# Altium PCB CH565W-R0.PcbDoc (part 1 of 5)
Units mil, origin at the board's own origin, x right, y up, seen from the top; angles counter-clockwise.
Board outline 3947.04 x 3947.04 mil, 4 copper layers (Top Layer, Layer 1, Layer 2, Bottom Layer), stack 23.756 mil thick; 204 components, 168 nets, 932 pads, 1005 vias.
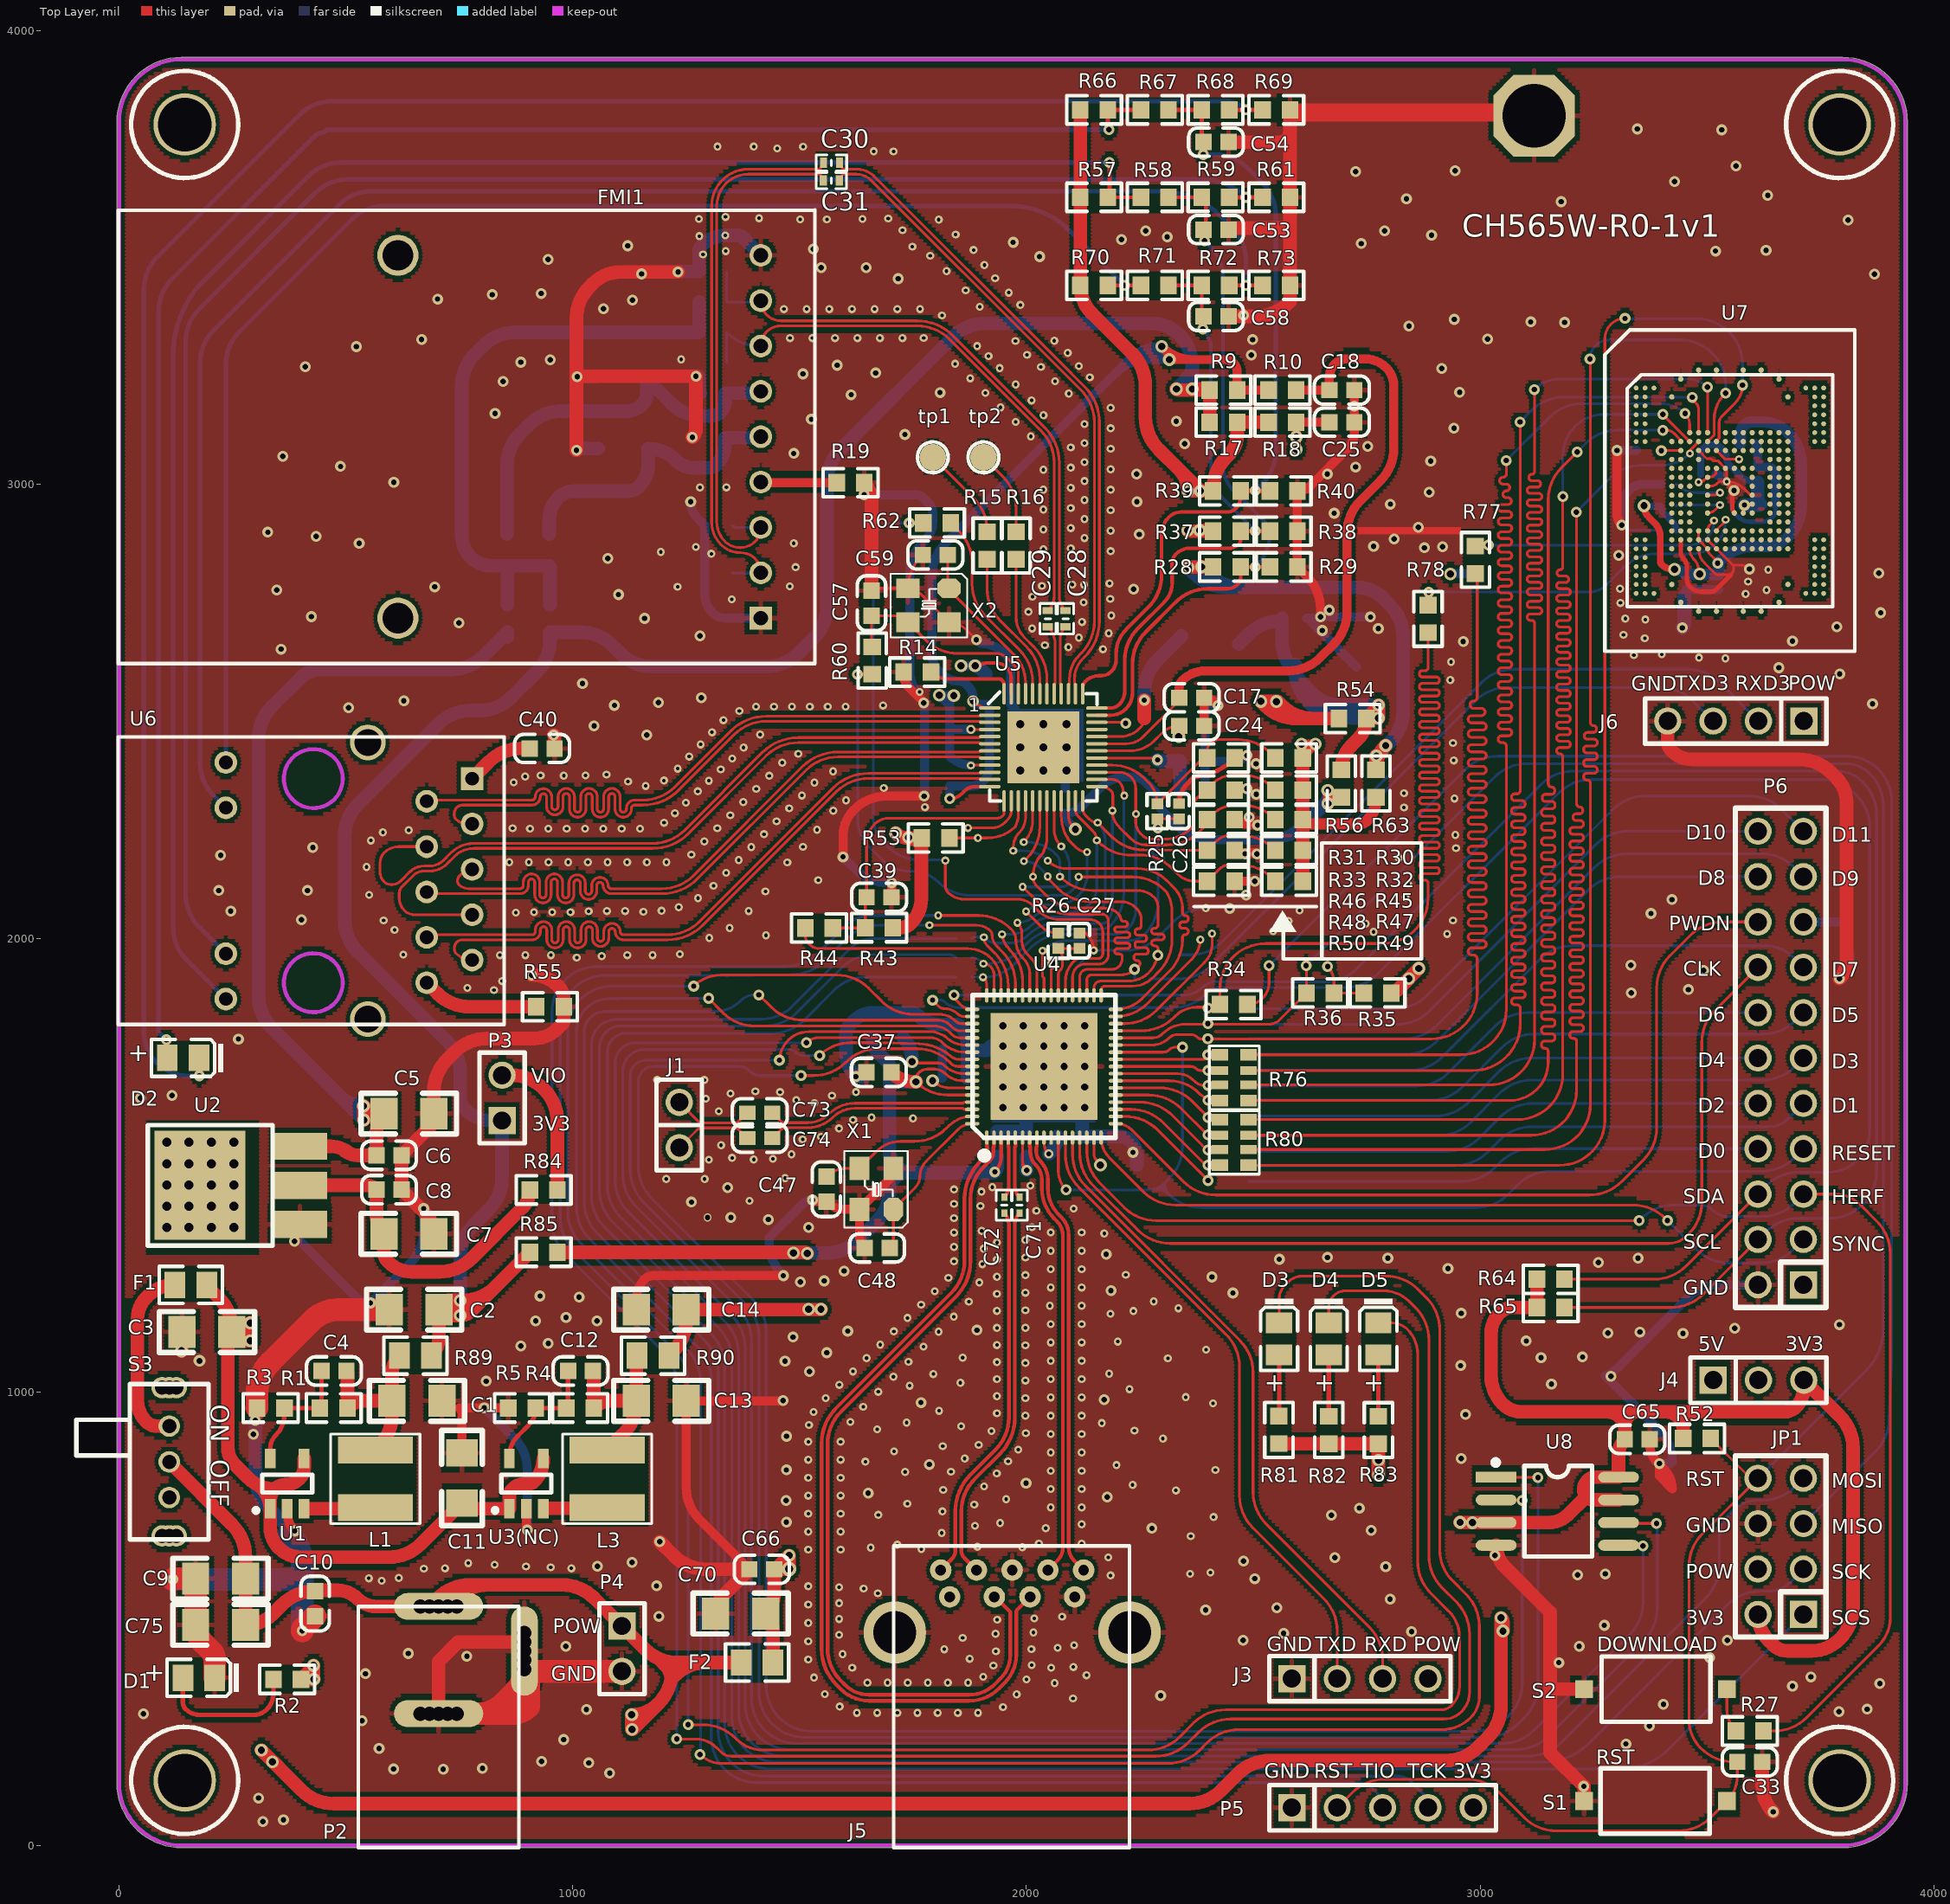
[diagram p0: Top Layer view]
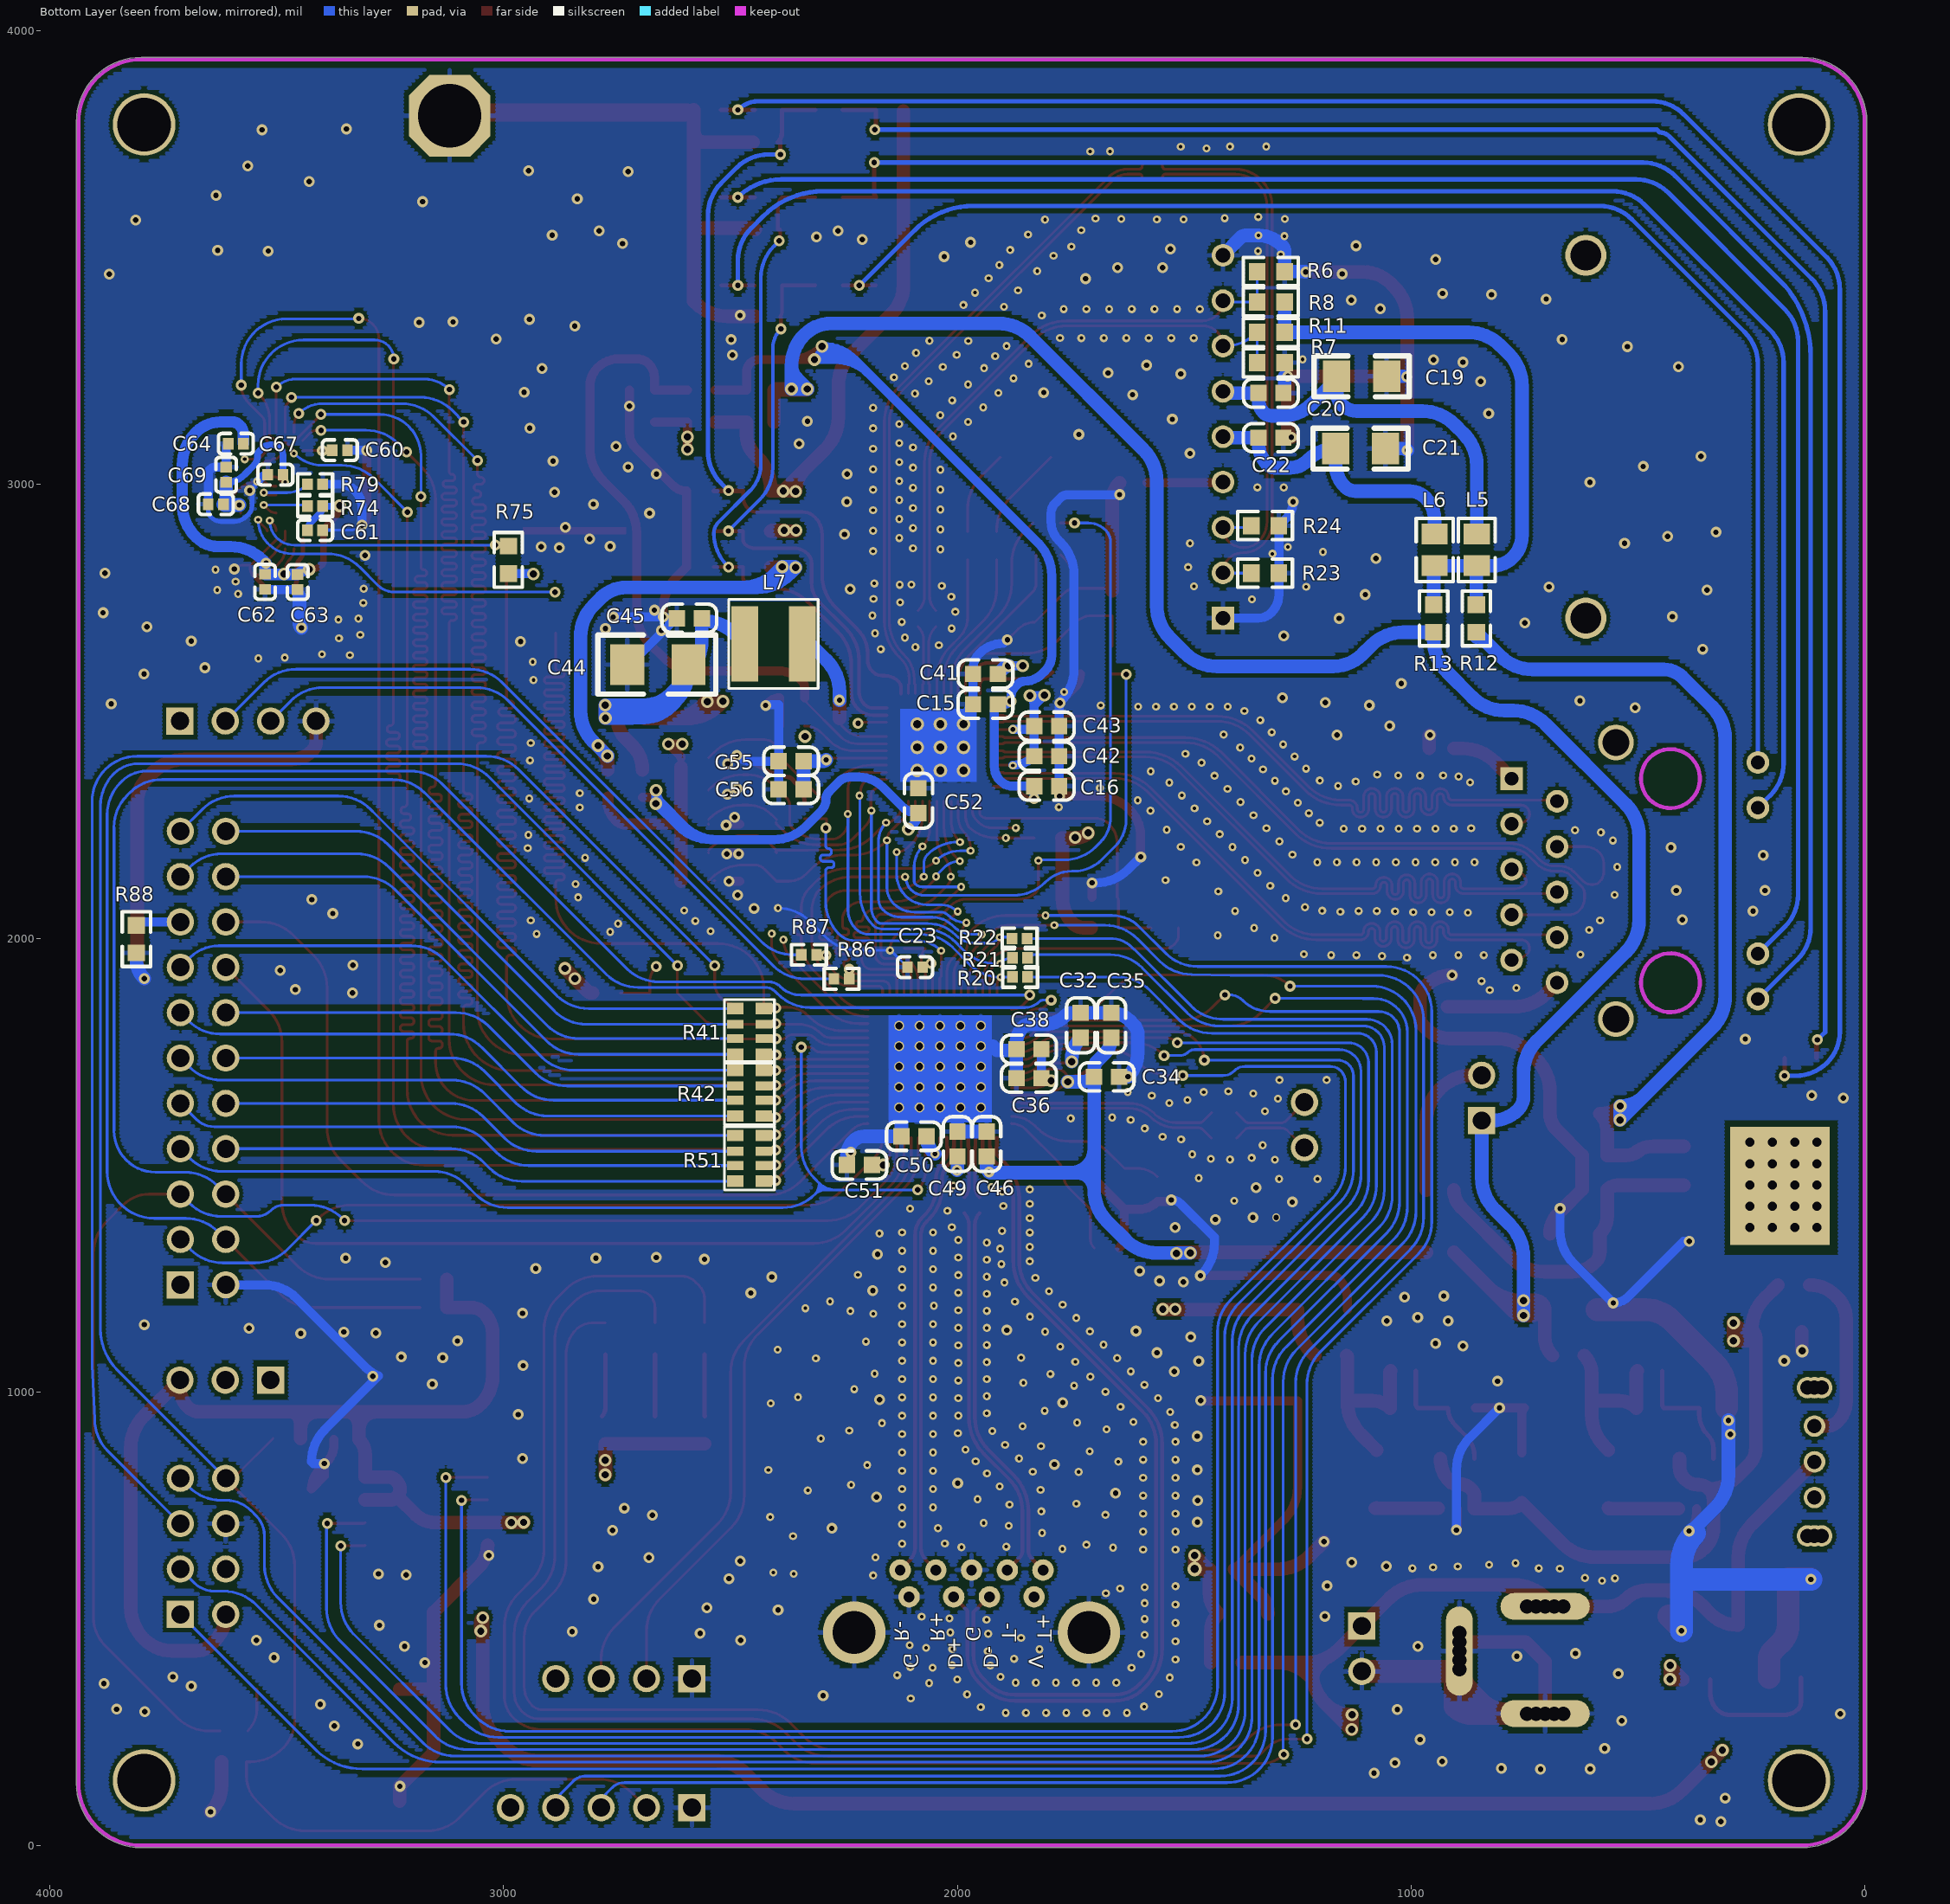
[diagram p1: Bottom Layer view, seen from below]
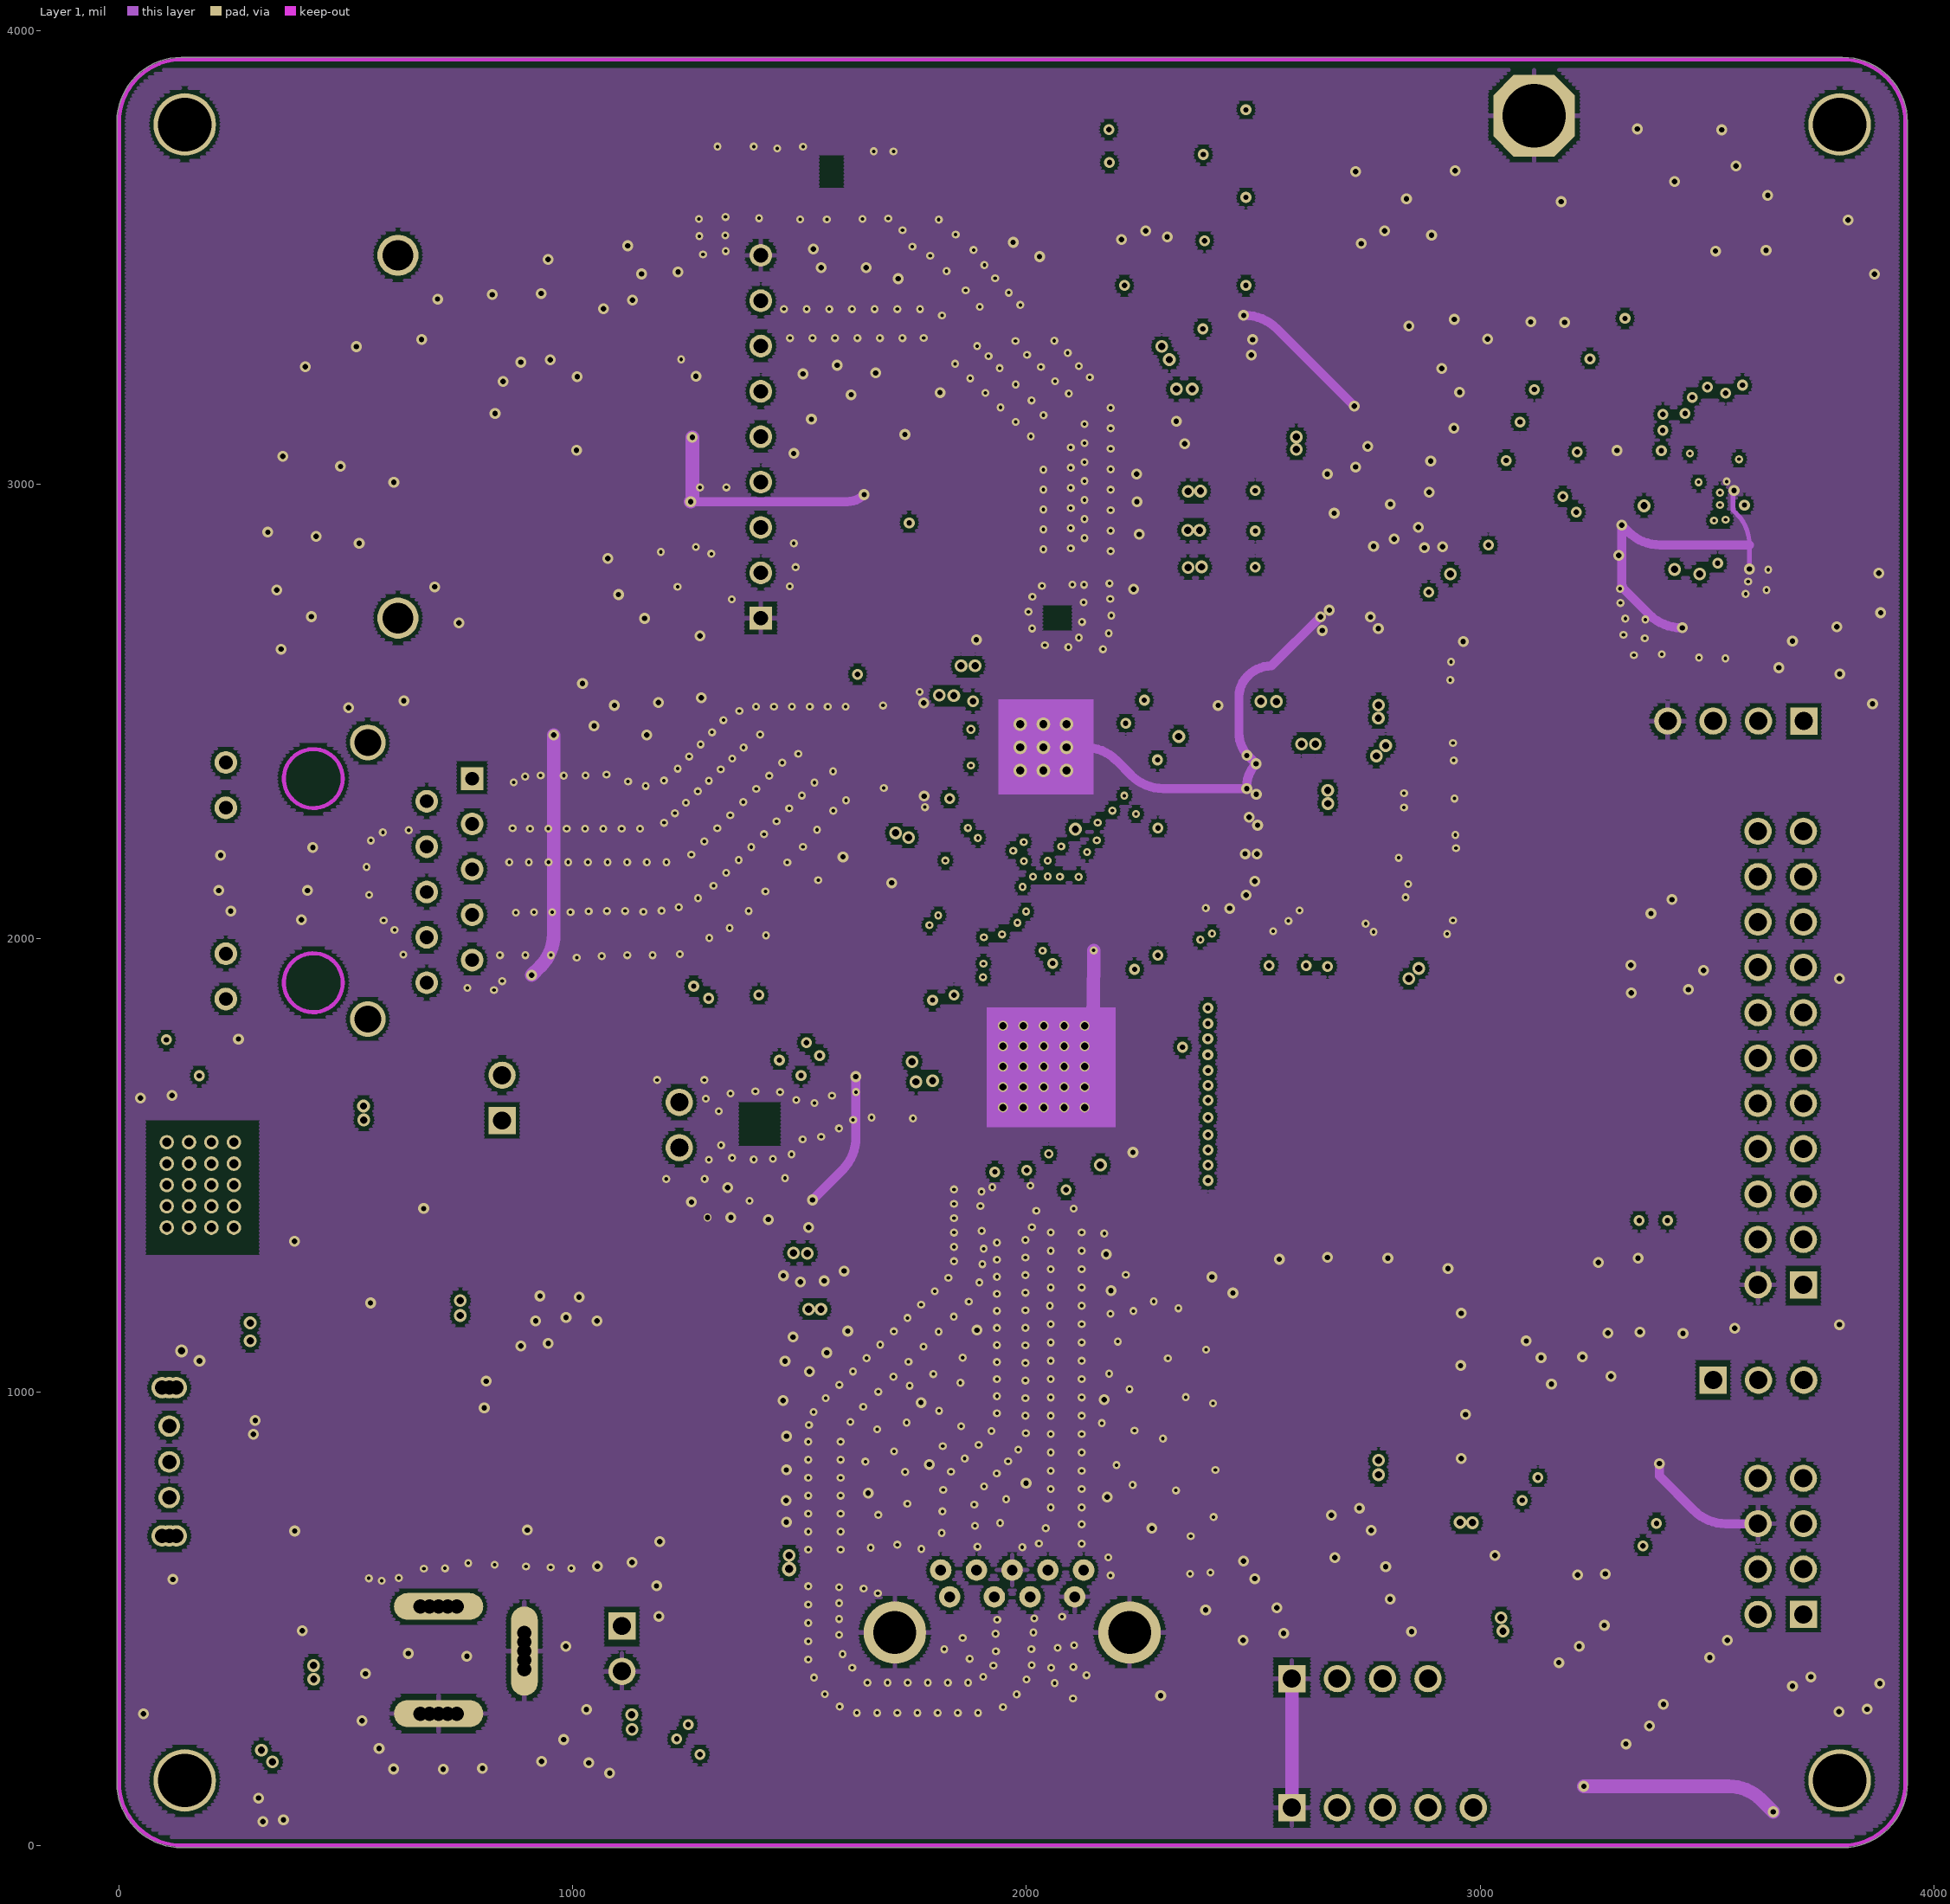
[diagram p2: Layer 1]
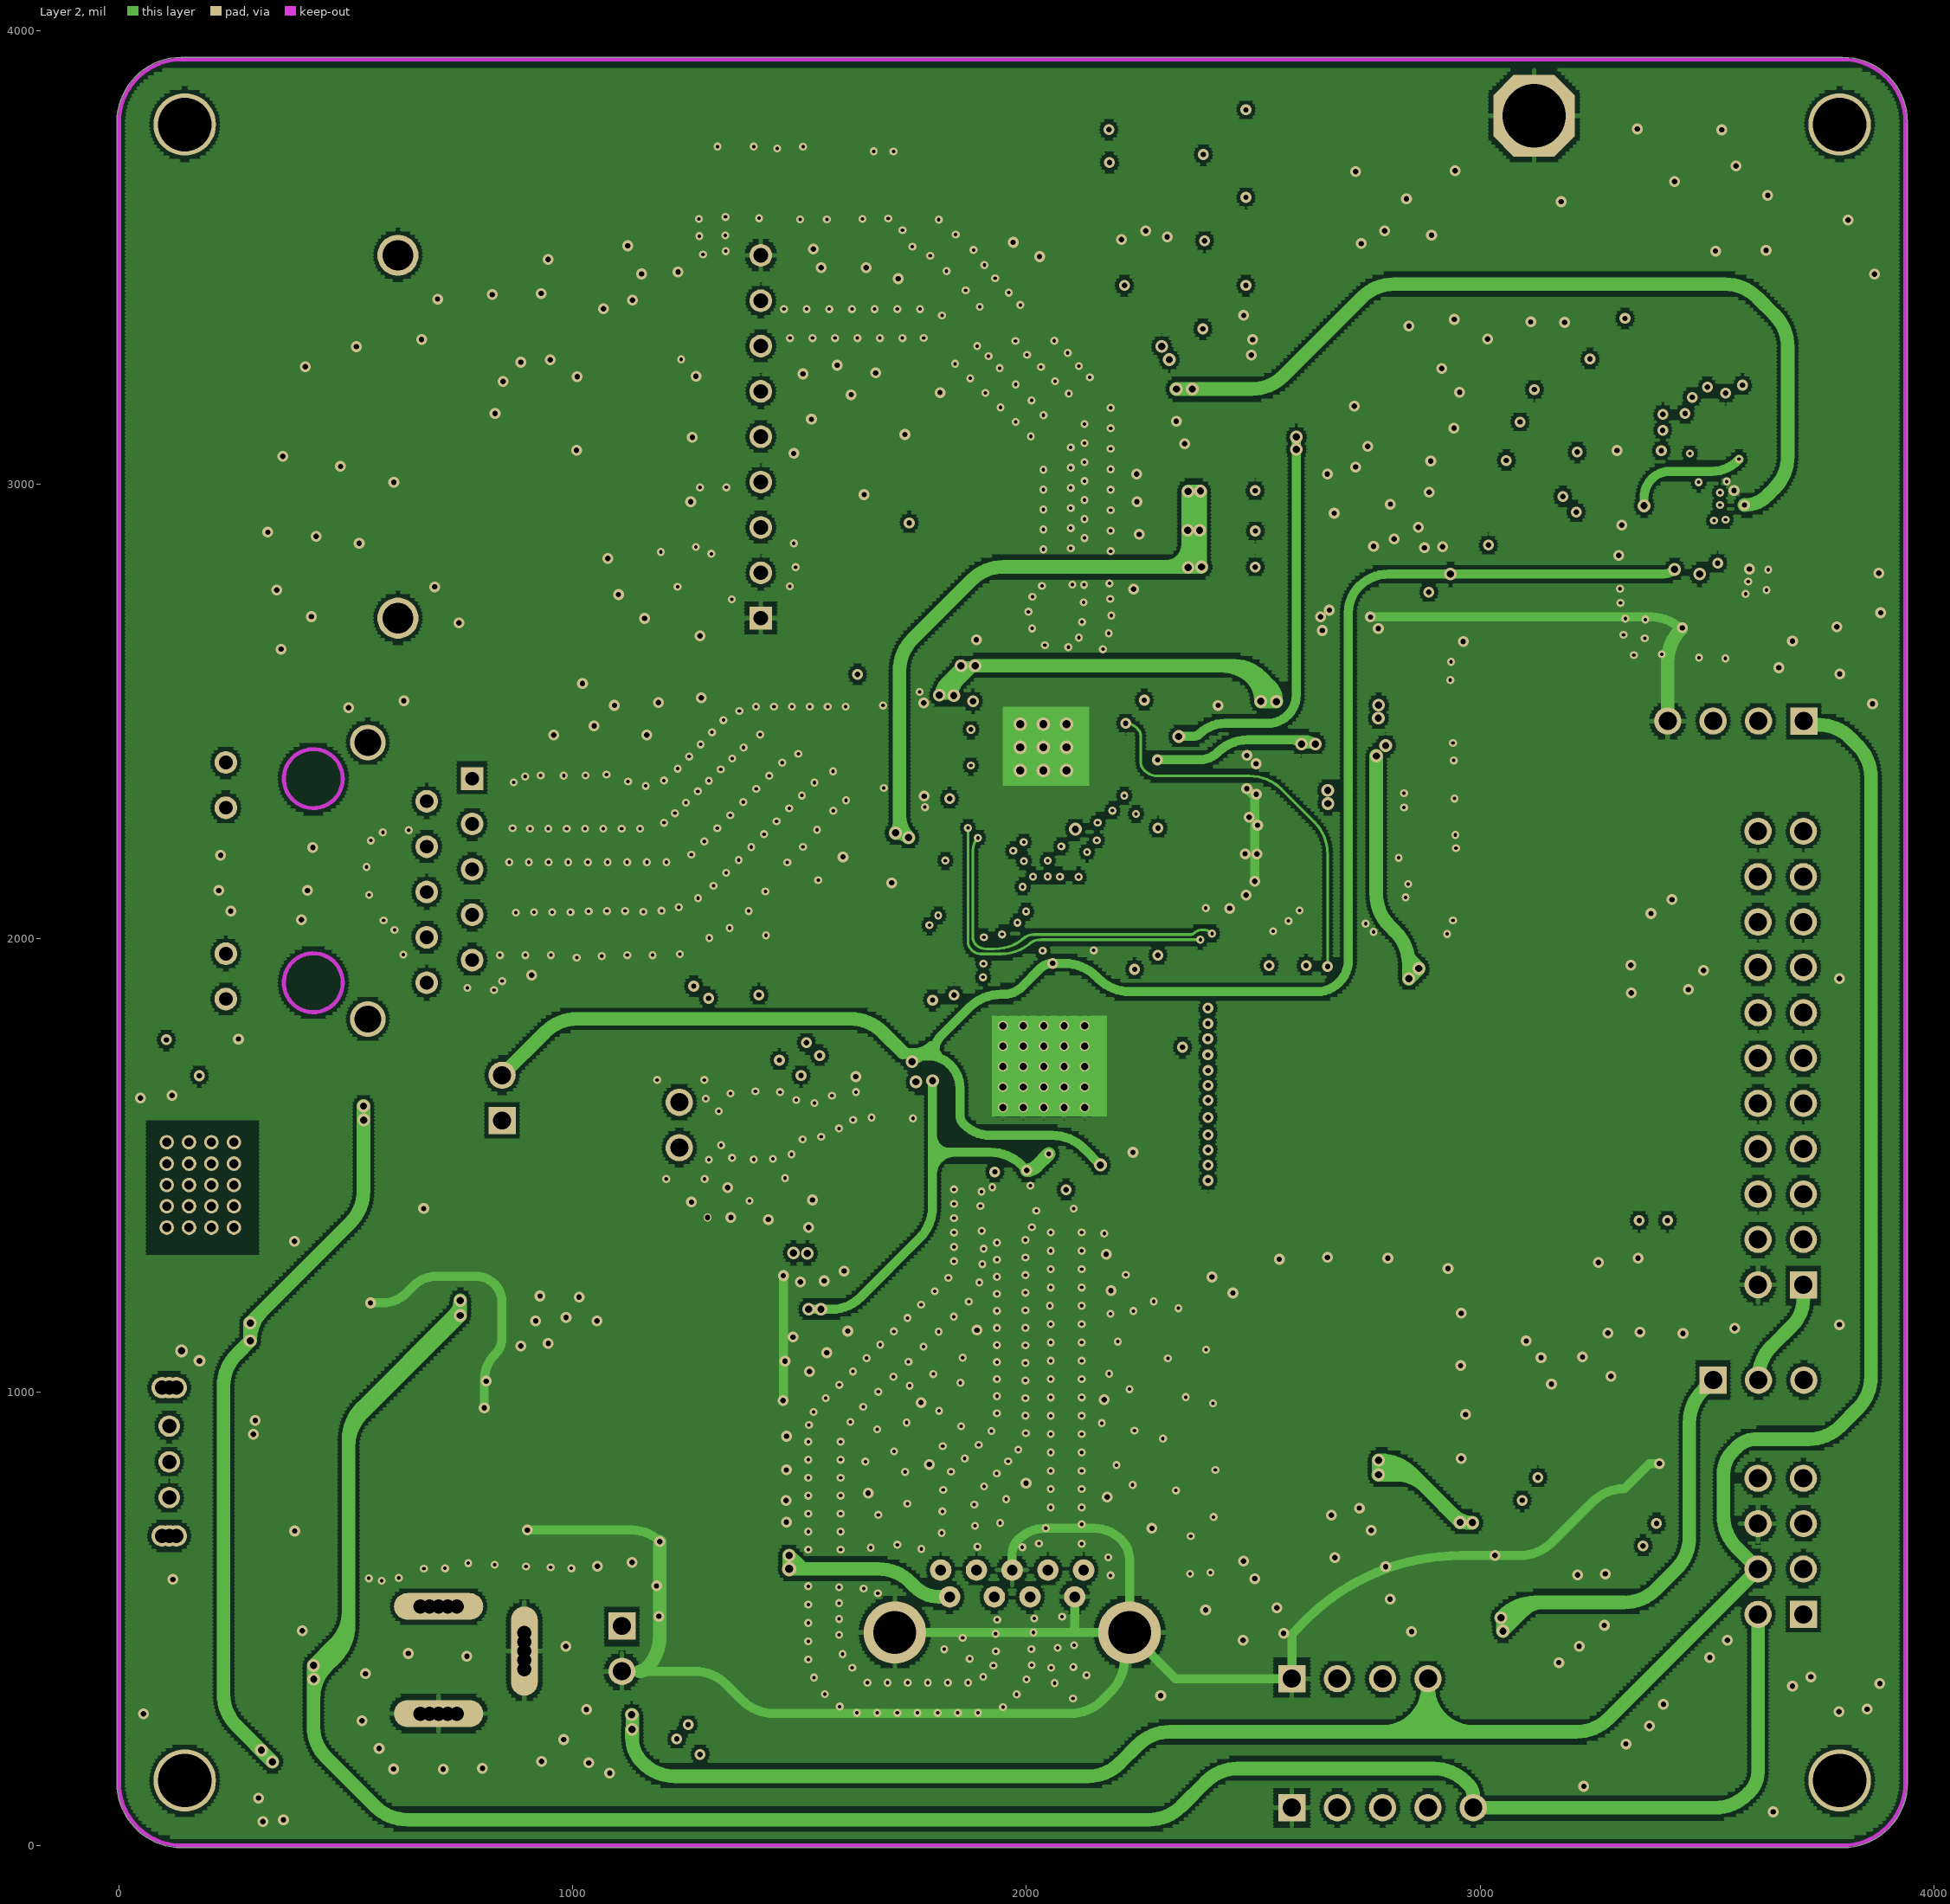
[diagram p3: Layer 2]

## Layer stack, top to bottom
Top Solder: solder mask 0.4, Solder Resist, Dk 3.5
Top Layer: signal copper 1.4
Dielectric 2: prepreg 2.8, PP-006, Dk 4.1
Layer 1: signal copper 1.378
Dielectric 3: prepreg 2.8, PP-006, Dk 4.1
Layer 2: signal copper 1.378
Dielectric 1: dielectric 12.6, FR-4, Dk 4.8
Bottom Layer: signal copper 1.4
Bottom Solder: solder mask 0.4, Solder Resist, Dk 3.5

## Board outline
-5.02,137.56 cw(c0,137.56) -5.01,137.68 cw(c0,137.8) -5.02,137.8 -5.02,3799.21 cw(c0,3799.21) -5.01,3799.38 cw(c0,3799.54) -5.02,3799.55 cw(c137.63,3799.38) 136.8,3942.02 cw(c137.63,3799.38) 136.97,3942.02 cw(c137.63,3799.38) 137.8,3942.02 136.97,3942.02 3799.21,3942.02 cw(c3799.21,3937.01) 3799.28,3942.02 cw(c3799.21,3799.21) 3942.02,3799.27 cw(c3937.01,3799.21) 3942.02,3799.21 3942.02,137.8 cw(c3937.01,137.8) 3942.02,137.74 ccw(c3799.36,137.65) 3942.02,137.8 ccw(c3799.36,137.65) 3942.02,137.8 3942.02,137.74 cw(c3799.36,137.65) 3942.02,137.65 cw(c3799.36,137.65) 3799.51,-5.01 cw(c3799.5,0) 3799.36,-5.01 cw(c3799.21,0) 3799.21,-5.01 137.79,-5.01 137.8,-5.01 cw(c137.68,137.68)

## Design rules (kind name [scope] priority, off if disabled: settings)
Clearance Clearance_2 [InPolygon] p1: gap=8 ignorepadtopadclearanceinfootprint=FALSE
Clearance Clearance_1 [IsVia] p2: gap=5 ignorepadtopadclearanceinfootprint=FALSE
Clearance [All] p3: gap=5 ignorepadtopadclearanceinfootprint=FALSE
ComponentClearance [All] p1 off: gap=10 collisioncheckmode=3 verticalgap=10 showdistances=FALSE
DiffPairsRouting [All] p1: maxlimit=10 minlimit=3.5 mostfreqgap=5 toplayer_minwidth=3.5 toplayer_maxwidth=20 toplayer_prefwidth=15 midlayer1_minwidth=3.5 midlayer1_maxwidth=20 midlayer1_prefwidth=15 midlayer2_minwidth=3.5 midlayer2_maxwidth=20 midlayer2_prefwidth=15 bottomlayer_minwidth=3.5 bottomlayer_maxwidth=20 bottomlayer_prefwidth=15 maxuncoupledlength=500
MinimumSolderMaskSliver [All] p1 off: minsoldermaskwidth=10
PolygonConnect PolygonConnect_1 [IsVia] p1: connectstyle=Direct reliefconductorwidth=10 reliefentries=4 polygonreliefangle="90 Angle" airgapwidth=10
PolygonConnect [All] p2: connectstyle=Relief reliefconductorwidth=10 reliefentries=4 polygonreliefangle="90 Angle" airgapwidth=10
RoutingVias [All] p1: holewidth=12 width=24 viastyle="Through Hole" minholewidth=7.87 minwidth=17.72 maxholewidth=28 maxwidth=50
SilkToSilkClearance [All] p1 off: silktosilkclearance=10
SilkToSolderMaskClearance [IsPad] p1 off: minsilkscreentomaskgap=10 clearancetoexposedcopper=TRUE
SolderMaskExpansion [All] p1: expansion=4 istentingtop=FALSE
Width [All] p1: maxlimit=60 minlimit=3.5 preferedwidth=30
25 further rules are at their usual default settings.

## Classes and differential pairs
differential pair EX: +EX_p -EX_n
differential pair HSI: +HSI_p -HSI_n
differential pair HSO_CK: +HSO_CK_p -HSO_CK_n
differential pair HSO: +HSO_p -HSO_n
differential pair MDI0: +MDI0_p -MDI0_n
differential pair MDI1: +MDI1_p -MDI1_n
differential pair MDI2: +MDI2_p -MDI2_n
differential pair MDI3: +MDI3_p -MDI3_n
differential pair RX: +RX_P -RX_N
differential pair SSRX: +SSRX_p -SSRX_n
differential pair SSTX: +SSTX_p -SSTX_n
differential pair TX: +TX_P -TX_N
differential pair UD: +UD_p -UD_n

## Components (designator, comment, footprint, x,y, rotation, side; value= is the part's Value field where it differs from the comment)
C1 "10uF" 3216 711.33,980.05 r0 top
C2 "100nF" 3216 595.06,1181.08 r180 top
C3 "10uF" 3216 138.32,1131.85 r180 top
C4 "22pF" 0603C#1 445.73,1045.86 r0 top
C5 "10uF" 3216 693.5,1613.32 r0 top
C6 "100nF" 0603C#1 622.28,1521.29 r180 top
C7 "10uF" 3216 693.5,1348.18 r0 top
C8 "100nF" 0603C#1 622.28,1445.69 r180 top
C9 "33uF" 3216 168.31,588.13 r180 top
C10 "100nF" 0603C#1 431.73,505.44 r90 top
C11 "NC(100nF)" 3216 755.6,865.01 r90 top
C12 "NC(20pF)" 0603C#1 989.47,1045.86 r0 top
C13 "NC(10uF)" 3216 1249.85,980.05 r0 top
C14 "NC(100nF)" 3216 1139.85,1181.08 r180 top
C15 "100nF" 0603C#1 1965.29,2515.77 r180 bottom
C16 "100nF" 0603C#1 1775.37,2335.2 r0 bottom
C17 "100nF" 0603C#1 2391.58,2530.02 r180 top
C18 "4.7uF" 0603C#1 2722.62,3208.28 r180 top
C19 "NC(10uF)" 3216 1163.53,3238.71 r0 bottom
C20 "NC(100nF)" 0603C#1 1336.16,3201.83 r180 bottom
C21 "NC(10uF)" 3216 1166.01,3079.34 r0 bottom
C22 "NC(100nF)" 0603C#1 1336.16,3103.34 r180 bottom
C23 "100nF" 0402C 2076.34,1936.13 r270 bottom
C24 "100nF" 0603C#1 2391.58,2467.96 r180 top
C25 "4.7uF" 0603C#1 2722.62,3137.48 r180 top
C26 "NC" 0402C 2336.45,2296.65 r0 top
C27 "NC" 0402C 2116.58,1977.58 r180 top
C28 "NC(100nF)" "C 0402_L"#1 2086.23,2704.42 r90 top
C29 "NC(100nF)" "C 0402_L"#1 2047.23,2704.42 r90 top
C30 "NC(100nF)" "C 0402_L"#1 1570.12,3709.36 r180 top
C31 "NC(100nF)" "C 0402_L"#1 1569.93,3670.39 r180 top
C32 "100nF" 0603C#1 1727.98,1780.45 r90 bottom
C33 "NC(100nF)" 0603C#1 3567.1,184.19 r0 top
C34 "100nF" 0603C#1 1698.35,1694.32 r180 bottom
C35 "3.3uF" 0603C#1 1660.22,1835.43 r270 bottom
C36 "100nF" 0603C#1 1869.62,1691.49 r180 bottom
C37 "100nF" 0603C#1 1647.17,1704.14 r0 top
C38 "3.3uF" 0603C#1 1869.62,1755.37 r180 bottom
C39 "100nF" 0603C#1 1702.57,2090.31 r180 top
C40 "100nF" 0603C#1 904.72,2418.14 r0 top
C41 "100nF" 0603C#1 1965.29,2582.46 r180 bottom
C42 "100nF" 0603C#1 1775.37,2401.28 r0 bottom
C43 "100nF" 0603C#1 1775.37,2467.37 r0 bottom
C44 "22uF" 3528 2727.47,2603.15 r0 bottom
C45 "100nF" 0603C#1 2618.17,2705.28 r180 bottom
C46 "100nF" 0603C#1 1935.23,1573.66 r270 bottom
C47 "20pF" 0603C#1 1558.97,1474.18 r270 top
C48 "20pF" 0603C#1 1643.26,1317 r0 top
C49 "100nF" 0603C#1 1999.49,1573.66 r270 bottom
C50 "100nF" 0603C#1 2123.11,1563.26 r180 bottom
C51 "100nF" 0603C#1 2243.18,1499.94 r180 bottom
C52 "100nF" 0603C#1 2085.63,2330.59 r270 bottom
C53 "100nF" 0603C#1 2390.39,3562.09 r0 top
C54 "100nF" 0603C#1 2390.39,3755.1 r0 top
C55 "100nF" 0603C#1 2393.75,2390.13 r180 bottom
C56 "4.7uF" 0603C#1 2393.75,2328.02 r180 bottom
C57 "27pF" 0603C#1 1658.43,2766.06 r270 top
C58 "100nF" 0603C#1 2390.39,3370.91 r0 top
C59 "27pF" 0603C#1 1771.58,2844.91 r0 top
C60 "1uF" 0402C 3377.84,3075.88 r90 bottom
C61 "4.7uF" 0402C 3432.34,2899.46 r90 bottom
C62 "100nF" 0402C 3526.13,2802.36 r180 bottom
C63 "100nF" 0402C 3454.09,2801.85 r180 bottom
C64 "100nF" 0402C 3573.76,3090.21 r270 bottom
C65 "100nF" 0603C#1 3374.03,895.12 r180 top
C66 "100nF" 0603C#1 1444.06,608.6 r180 top
C67 "4.7uF" 0402C 3486.52,3021.86 r270 bottom
C68 "100nF" 0402C 3617.9,2956.7 r270 bottom
C69 "100nF" 0402C 3611.87,3004.9 r0 bottom
C70 "10uF" 3216 1424.93,510.97 r0 top
C71 "100nF" "C 0402_L"#2 1984.51,1411.34 r270 top
C72 "100nF" "C 0402_L"#2 1951.01,1411.34 r270 top
C73 "NC(100nF)" 0603C#2 1439.59,1615.2 r180 top
C74 "NC(100nF)" 0603C#2 1439.59,1559.12 r180 top
C75 "NC(33uF)" 3216 168.31,486.14 r180 top
D1 "LED1" 0805+ 140.35,369.48 r0 top
D2 "blue 0805" 0805+ 105.9,1736.01 r0 top
D3 "Green 0805" 0805+ 2557.01,1081.6 r90 top
D4 "Blue 0805" 0805+ 2666.38,1081.6 r90 top
D5 "Yellow 0805" 0805+ 2775.75,1081.6 r90 top
F1 "1A" 0805 122.84,1235.6 r0 top
F2 "1A" 0805 1441.23,402.99 r180 top
FMI1 "NC(PT8351)" PT8351 1414.36,2705.51 r180 top
J1 "CON2(NC)" SIP2-2.54mm#1 1234.59,1638.12 r0 top
J3 "CON4" SIP4-2.54mm 2585.09,367.45 r90 top
J4 "CON3" SIP3-2.54mm 3513.66,1025.68 r90 top
J5 "USB-AF3.0" USB3.0-A-Receptacle 1830.72,547.91 r0 top
J6 "CON4" SIP4-2.54mm 3713.66,2478.72 r270 top
JP1 "HEADER 4X2" IDC8-2.54mm 3712.66,509.23 r180 top
L1 "*" SMD_5x5mm 564.59,744.24 r90 top
L3 "NC(3.3uH)" SMD_5x5mm 1075.53,744.24 r90 top
L5 "NC(100mH)" 0805 854.63,2821.07 r90 bottom
L6 "NC(100mH)" 0805 947.63,2821.07 r90 bottom
L7 "2.2uH" SMD_5x5mm 2341.44,2648.83 r0 bottom
P2 "POWER_JACK" DC-005 704.07,526.67 r90 top
P3 "Header 2" SIP2-2.54mm#2 843.97,1597.92 r0 top
P4 "Header 2" SIP2-2.54mm#2 1108.22,483.63 r180 top
P5 "Header 5" SIP5-2.54mm 2585.09,83.11 r90 top
P6 "Header 11X2" IDC22-2.54mm 3712.66,1235.79 r180 top
R1 "10K" 0603 503.06,964.09 r180 top
R2 "1K" 0603 339.95,365.91 r0 top
R3 "2.2K" 0603 303.6,964.09 r0 top
R4 "NC(10K)" 0603 1046.15,964.09 r180 top
R5 "NC(10K)" 0603 857.74,964.09 r0 top
R6 "NC(180Ω)" 0603 1338.98,3469.48 r180 bottom
R7 "NC(180Ω)" 0603 1338.98,3268.74 r180 bottom
R8 "NC(68Ω)" 0603 1338.98,3402.57 r180 bottom
R9 "0Ω" 0603 2403.9,3208.28 r0 top
R10 "0Ω" 0603 2533.95,3208.28 r0 top
R11 "NC(68Ω)" 0603 1338.98,3335.66 r180 bottom
R12 "NC(0Ω)" 0603 855.52,2674.67 r90 bottom
R13 "NC(0Ω)" 0603 949.8,2674.67 r90 bottom
R14 "2.49K 1%" 0603 1789.55,2586.75 r180 top
R15 "NC(0Ω)" 0603 1913.28,2895.75 r270 top
R16 "NC(0Ω)" 0603 1977.14,2895.75 r270 top
R17 "0Ω" 0603 2403.9,3137.48 r0 top
R18 "0Ω" 0603 2533.95,3137.48 r0 top
R19 "NC(4.7KΩ)" 0603 1642.47,3004.25 r180 top
R20 "NC(0R)" 0402 1878.26,1914.38 r180 bottom
R21 "NC(0R)" 0402 1878.52,1957.02 r180 bottom
R22 "NC(0R)" 0402 1879.11,1999.15 r180 bottom
R23 "NC(270Ω)" 0603 1291.18,2804.76 r0 bottom
R24 "NC(270Ω)" 0603 1291.18,2909.48 r0 bottom
R25 "0Ω" 0402 2288.5,2263.11 r90 top
R26 "0Ω" 0402 2070.34,2010.74 r270 top
R27 "0Ω" 0603 3624.9,252.09 r180 top
R28 "4.7K" 0603 2411.47,2818.39 r0 top
R29 "NC" 0603 2536.59,2818.39 r0 top
R30 "NC" 0603 2609.22,2397.59 r180 top
R31 "4.7K" 0603 2398.43,2397.59 r0 top
R32 "NC" 0603 2609.22,2326.58 r180 top
R33 "4.7K" 0603 2398.43,2326.58 r0 top
R34 "0Ω" 0603 2426.43,1853.87 r0 top
R35 "4.7K" 0603 2743.57,1879.13 r0 top
R36 "NC(0Ω)" 0603 2677.86,1879.13 r180 top
R37 "NC" 0603 2411.47,2897.13 r0 top
R38 "4.7K" 0603 2536.59,2897.13 r0 top
R39 "NC" 0603 2411.47,2985.87 r0 top
R40 "4.7K" 0603 2536.59,2985.87 r0 top
R41 "33R" RCA-8P4R-0603 2458.02,1794.33 r270 bottom
R42 "33R" RCA-8P4R-0603 2458.02,1658.42 r90 bottom
R43 "4.7K" 0603 1644.77,2023.17 r0 top
R44 "0Ω" 0603 1573.01,2022.43 r180 top
R45 "NC" 0603 2609.22,2261.58 r180 top
R46 "4.7K" 0603 2398.43,2261.58 r0 top
R47 "NC" 0603 2609.22,2193.57 r180 top
R48 "4.7K" 0603 2398.43,2193.57 r0 top
R49 "NC" 0603 2609.22,2125.57 r180 top
R50 "4.7K" 0603 2398.43,2125.57 r0 top
R51 "33R" RCA-8P4R-0603 2458.02,1514.59 r90 bottom
R52 "10K" 0603 3508.47,897.08 r180 top
R53 "4.7K" 0603 1769.44,2220.81 r0 top
R54 "0Ω" 0603 2749.47,2484.02 r180 top
R55 "0Ω" 0603 919.3,1848.76 r0 top
R56 "0Ω" 0603 2694.06,2371.24 r270 top
R57 "510Ω" 0603 2118.6,3633.33 r0 top
R58 "NC" 0603 2252.54,3633.33 r0 top
R59 "0Ω" 0603 2447.11,3633.33 r180 top
R60 "0Ω" 0603 1659.93,2642.4 r270 top
R61 "NC" 0603 2520.42,3633.33 r0 top
R62 "0Ω" 0603 1833.08,2915.44 r180 top
R63 "0Ω" 0603 2770.33,2310.61 r90 top
R64 "10K" 0603 3185.89,1248.07 r180 top
R65 "10K" 0603 3185.89,1185.93 r180 top
R66 "NC(510Ω)" 0603 2118.6,3826.22 r0 top
R67 "0Ω" 0603 2252.54,3826.22 r0 top
R68 "NC" 0603 2447.11,3826.22 r180 top
R69 "510Ω" 0603 2520.42,3826.22 r0 top
R70 "NC" 0603 2118.6,3439.1 r0 top
R71 "0Ω" 0603 2252.54,3439.1 r0 top
R72 "NC" 0603 2447.11,3439.1 r180 top
R73 "510Ω" 0603 2520.42,3439.1 r0 top
R74 "33Ω" 0402 3398.87,2952.28 r0 bottom
R75 "10K" 0603 2989.6,2803.67 r90 bottom
R76 "33R" RCA-8P4R-0603 2458.02,1692.43 r270 top
R77 "33Ω" 0603 2989.6,2864.3 r270 top
R78 "33Ω" 0603 2885.32,2734.3 r270 top
R79 "1K" 0402 3432.34,3000.83 r180 bottom
R80 "33R" RCA-8P4R-0603 2458.02,1549.7 r270 top
R81 "1K" 0603 2556.38,946.26 r270 top
R82 "1K" 0603 2666.38,946.08 r270 top
R83 "1K" 0603 2775.75,945.83 r270 top
R84 "0Ω" 0603 905.3,1445.02 r0 top
R85 "0Ω" 0603 905.3,1307.5 r0 top
R86 "NC(0Ω)" 0402 2271.88,1910.43 r180 bottom
R87 "NC(0Ω)" 0402 2343.67,1963.28 r180 bottom
R88 "NC(0Ω)" 0603 3809.64,1967.68 r90 bottom
R89 "0Ω" 0805 617.88,1079.72 r0 top
R90 "0Ω" 0805 1141.72,1079.72 r0 top
S1 "SW-PB" SMD_6.1x3.65x2.5mm-KEY 3544.26,97.75 r180 top
S2 "SW-PB" SMD_6.1x3.65x2.5mm-KEY 3229.3,344.38 r0 top
S3 "SW-SPDT" "Horizontal Slide Switch_8.7x4.4mm-2D" 23.56,1016.84 r270 top
tp1 "test-point" TESTPOINT1 1793.44,3060.12 r0 top
tp2 "test-point" TESTPOINT1 1905.1,3060.12 r0 top
U1 "8502AM" SOT-23-5 332.87,742.39 r0 top
U2 "1117-3.3V" SOT-223 398.07,1369.16 r90 top
U3(NC) "8502AM" SOT-23-5 860,742.39 r0 top
U4 "CH565W" QFN68_8X8 2038.59,1717.12 r0 top
U5 "RTL8211FS" QFN48_6X6 1919.13,2507.41 r0 top
U6 "HR911130C" HR911130C 777.86,2351.78 r90 top
U7 "MTFC16GJVEC-4M IT" WFBGA-169-14x18x0.8mm 3422.73,3114.53 r0 top
U8 "W25Q32JV" SOIC-8_208mil 3035.36,811.58 r0 top
X1 "30MHz" 3225 1631.8,1402.13 r90 top
X2 "25MHz" 3225 1829.29,2696.56 r180 top

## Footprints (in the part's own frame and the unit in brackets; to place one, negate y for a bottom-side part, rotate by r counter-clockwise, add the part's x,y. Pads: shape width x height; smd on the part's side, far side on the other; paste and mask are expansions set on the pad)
0402 [mm]
  rect 0.6x0.65 smd mask+0.051: 1(0,0) 2(0.85,0)
  silkscreen extent -0.55,-0.58 1.4,0.57
0402C [mm]
  rect 0.65x0.6 smd mask+0.051: 1(0,0) 2(0,-0.85)
  silkscreen extent -0.58,-1.4 0.57,0.55
0603 [mm]
  rect 0.93x0.98 smd: 1(0,0) 2(1.54,0)
  silkscreen extent -0.76,-0.79 2.3,0.79
0603C#1 [mil]
  rect 36x36 smd: 1(0,0) 2(55,0)
  silkscreen extent -33,-31 88,31
0603C#2 [mil]
  rect 36x31.08 smd: 1(0,0) 2(55,0)
  silkscreen extent -33,-31 88,31
0805 [mm]
  rect 1.16x1.47 smd: 1(0,0) 2(1.78,0)
  silkscreen extent -0.88,-1.04 2.66,1.03
0805+ [mm]
  rect 1.16x1.47 smd: 1(0,0) 2(1.78,0)
  silkscreen extent -0.88,-1.04 3.13,1.03
3216 [mil]
  rect 60x70 smd: 1(0,0) 2(-110,0)
  silkscreen extent -160,-45 50,45
3225 [mm]
  oct 1.3x1.1 smd: 1(0,-1.9)
  rect 1.3x1.1 smd: 2(2.3,-1.9) 3(2.3,0) 4(0,0)
  silkscreen extent -1.02,-2.7 3.27,0.84
3528 [mil]
  rect 75x90 smd: 1(0,0) 2(-135,0)
  silkscreen extent -195,-65 65,65
"C 0402_L"#1 [mm]
  rect 0.4x0.584 smd: 1(-0.45,0) 2(0.45,0)
  silkscreen extent -0.85,-0.45 0.85,0.45, body extent -0.5,-0.26 0.5,0.26, height 0.53
"C 0402_L"#2 [mm]
  rect 0.4x0.343 smd: 1(-0.45,0) 2(0.45,0)
  silkscreen extent -0.85,-0.45 0.85,0.45, body extent -0.5,-0.26 0.5,0.26, height 0.53
DC-005 [mm]
  round 1 hole 0.8: 1(0,1.016) 1(0,0.508) 1(0,-0.508) 1(0,-1.016) 2(-6,-1.016) 2(-6,-0.508) 2(-6,0.508) 2(-6,1.016) 3(-3.516,-4.8) 3(-3.008,-4.8) 3(-1.992,-4.8) 3(-1.484,-4.8)
  oval 1.5x5 hole 0.8: 1(0,0) 2(-6,0)
  oval 5x1.5 hole 0.8: 3(-2.5,-4.8)
  silkscreen extent -13.5,-4.5 0,4.5
"Horizontal Slide Switch_8.7x4.4mm-2D" [mm]
  round 1.2 hole 0.8: 0(0.2,2.6) 0(0.2,2.2) 0(0.2,1.8) 0(8.5,1.8) 0(8.5,2.2) 0(8.5,2.6) 1(4.35,2.2) 2(2.35,2.2) 3(6.35,2.2)
  silkscreen extent 0,-3 8.7,4.4
HR911130C [mil]
  round 78.74 hole 59.06: 0(-529.99,229.92) 0(79.85,229.92)
  rect 50x50 hole 30: 1(0,0)
  round 50 hole 30: 2(-50,100) 3(-100,0) 4(-150,100) 5(-200,0) 6(-250,100) 7(-300,0) 8(-350,100) 9(-400,0) 10(-450,100) 11(35.76,542.91) 12(-64.24,542.91) 13(-385.9,542.91) 14(-485.9,542.91)
  Keep-Out Layer circle w9: c0,350 r65
  Keep-Out Layer circle w9: c-450,350 r65
  silkscreen extent -542,-70 92,780
IDC8-2.54mm [mil]
  rect 60x60 hole 40: 1(0,0)
  round 60 hole 40: 2(100,0) 3(0,-100) 4(100,-100) 5(0,-200) 6(100,-200) 7(0,-300) 8(100,-300)
  silkscreen extent -50,-350 150,50
IDC22-2.54mm [mil]
  rect 60x60 hole 40: 1(0,0)
  round 60 hole 40: 2(100,0) 3(0,-100) 4(100,-100) 5(0,-200) 6(100,-200) 7(0,-300) 8(100,-300) 9(0,-400) 10(100,-400) 11(0,-500) 12(100,-500) 13(0,-600) 14(100,-600) 15(0,-700) 16(100,-700) 17(0,-800) 18(100,-800) 19(0,-900) 20(100,-900) 21(0,-1000) 22(100,-1000)
  silkscreen extent -50,-1051 150,50
PT8351 [mil] "1.25GHz,1550nm激?"
  rect 50x50 hole 32: 1(0,0)
  round 50 hole 32: 2(0,-100) 3(0,-200) 4(0,-300) 5(0,-400) 6(0,-500) 7(0,-600) 8(0,-700) 9(0,-800)
  round 90.55 hole 66.93: 10(800,0) 11(800,-800)
  silkscreen extent -119,-900 1416,100
QFN48_6X6 [mm]
  oval 1.2x0.2 smd: 1(0,0) 2(0,-0.4) 3(0,-0.8) 4(0,-1.2) 5(0,-1.6) 6(0,-2) 7(0,-2.4) 8(0,-2.8) 9(0,-3.2) 10(0,-3.6) 11(0,-4) 12(0,-4.4) 25(6,-4.4) 26(6,-4) 27(6,-3.6) 28(6,-3.2) 29(6,-2.8) 30(6,-2.4) 31(6,-2) 32(6,-1.6) 33(6,-1.2) 34(6,-0.8) 35(6,-0.4) 36(6,0)
  oval 0.2x1.2 smd: 13(0.8,-5.2) 14(1.2,-5.2) 15(1.6,-5.2) 16(2,-5.2) 17(2.4,-5.2) 18(2.8,-5.2) 19(3.2,-5.2) 20(3.6,-5.2) 21(4,-5.2) 22(4.4,-5.2) 23(4.8,-5.2) 24(5.2,-5.2) 37(5.2,0.8) 38(4.8,0.8) 39(4.4,0.8) 40(4,0.8) 41(3.6,0.8) 42(3.2,0.8) 43(2.8,0.8) 44(2.4,0.8) 45(2,0.8) 46(1.6,0.8) 47(1.2,0.8) 48(0.8,0.8)
  round 0.762 hole 0.457: 49(1.7,-3.5) 49(1.7,-2.2) 49(1.7,-0.9) 49(3,-3.5) 49(3,-2.2) 49(3,-0.9) 49(4.3,-3.5) 49(4.3,-2.2) 49(4.3,-0.9)
  rect 4x4 smd: 49(3,-2.2)
  silkscreen extent -0.08,-5.2 6,0.89
QFN68_8X8 [mm]
  round 0.559 hole 0.406: 0(-2.299,-2.293) 0(-2.299,-1.149) 0(-2.299,-0.006) 0(-2.299,1.138) 0(-2.299,2.281) 0(-1.155,-2.293) 0(-1.155,-1.149) 0(-1.155,-0.006) 0(-1.155,1.138) 0(-1.155,2.281) 0(-0.012,-2.293) 0(-0.012,-1.149) 0(-0.012,-0.006) 0(-0.012,1.138) 0(-0.012,2.281) 0(1.132,-2.293) 0(1.132,-1.149) 0(1.132,-0.006) 0(1.132,1.138) 0(1.132,2.281) 0(2.275,-2.293) 0(2.275,-1.149) 0(2.275,-0.006) 0(2.275,1.138) 0(2.275,2.281)
  rect 6x6 smd: 0(0,0)
  oval 0.2x0.8 smd: 1(-3.2,-3.982) 2(-2.8,-3.982) 3(-2.4,-3.982) 4(-2,-3.982) 5(-1.6,-3.982) 6(-1.2,-3.982) 7(-0.8,-3.982) 8(-0.4,-3.982) 9(0,-3.982) 10(0.4,-3.982) 11(0.8,-3.982) 12(1.2,-3.982) 13(1.6,-3.982) 14(2,-3.982) 15(2.4,-3.982) 16(2.8,-3.982) 17(3.2,-3.982) 35(3.2,3.982) 36(2.8,3.982) 37(2.4,3.982) 38(2,3.982) 39(1.6,3.982) 40(1.2,3.982) 41(0.8,3.982) 42(0.4,3.982) 43(0,3.982) 44(-0.4,3.982) 45(-0.8,3.982) 46(-1.2,3.982) 47(-1.6,3.982) 48(-2,3.982) 49(-2.4,3.982) 50(-2.8,3.982) 51(-3.2,3.982)
  oval 0.8x0.2 smd: 18(4.018,-3.2) 19(4.018,-2.8) 20(4.018,-2.4) 21(4.018,-2) 22(4.018,-1.6) 23(4.018,-1.2) 24(4.018,-0.8) 25(4.018,-0.4) 26(4.018,0) 27(4.018,0.4) 28(4.018,0.8) 29(4.018,1.2) 30(4.018,1.6) 31(4.018,2) 32(4.018,2.4) 33(4.018,2.8) 34(4.018,3.2) 52(-4.018,3.2) 53(-4.018,2.8) 54(-4.018,2.4) 55(-4.018,2) 56(-4.018,1.6) 57(-4.018,1.2) 58(-4.018,0.8) 59(-4.018,0.4) 60(-4.018,0) 61(-4.018,-0.4) 62(-4.018,-0.8) 63(-4.018,-1.2) 64(-4.018,-1.6) 65(-4.018,-2) 66(-4.018,-2.4) 67(-4.018,-2.8) 68(-4.018,-3.2)
  silkscreen extent -4,-5.19 4,4
RCA-8P4R-0603 [mm]
  rect 0.65x0.9 smd: 1(-1.28,-0.8) 4(1.28,-0.8) 5(1.28,0.8) 8(-1.28,0.8)
  rect 0.5x0.9 smd: 2(-0.4,-0.8) 3(0.4,-0.8) 6(0.4,0.8) 7(-0.4,0.8)
  silkscreen extent -1.78,-1.4 1.78,1.4, body extent -1.6,-0.8 1.6,0.8, height 0.6
SIP2-2.54mm#1 [mil]
  round 60 hole 40: 1(0,0) 2(0,-100)
  silkscreen extent -50,-150 50,50
SIP2-2.54mm#2 [mil]
  rect 60x60 hole 40: 1(0,0)
  round 60 hole 40: 2(0,100)
  silkscreen extent -50,-50 50,150
SIP3-2.54mm [mil]
  rect 60x60 hole 40: 1(0,0)
  round 60 hole 40: 2(0,-100) 3(0,-200)
  silkscreen extent -50,-250 50,50
SIP4-2.54mm [mil]
  rect 60x60 hole 40: 1(0,0)
  round 60 hole 40: 2(0,-100) 3(0,-200) 4(0,-300)
  silkscreen extent -50,-350 50,50
SIP5-2.54mm [mil]
  rect 60x60 hole 40: 1(0,0)
  round 60 hole 40: 2(0,-100) 3(0,-200) 4(0,-300) 5(0,-400)
  silkscreen extent -50,-450 50,50
SMD_5x5mm [mm]
  rect 1.5x4.2 smd: 1(0,0) 2(3.23,0)
  silkscreen extent -0.88,-2.5 4.12,2.5
SMD_6.1x3.65x2.5mm-KEY [mm]
  rect 1x1 smd: 1(0,0) 2(8,0)
  silkscreen extent 0.98,-1.83 7.08,1.83
SOIC-8_208mil [mil]
  rect 90x24 smd: 1(0,0)
  oval 90x24 smd: 2(0,-50) 3(0,-100) 4(0,-150) 5(270,-150) 6(270,-100) 7(270,-50) 8(270,0)
  silkscreen extent -7,-175 212,38
SOT-23-5 [mm]
  rect 0.6x1.1 smd: 1(0,0) 2(0.95,0) 3(1.9,0) 4(1.9,2.8) 5(0,2.8)
  silkscreen extent -0.92,-0.22 2.35,1.9
SOT-223 [mil]
  rect 60x120 smd: 1(0,0) 2(86,0) 3(172,0)
  rect 240x200 smd: ""(86,220)
  silkscreen extent -47,60 219,335
TESTPOINT1 [mm]
  round 1.5 smd: 1(0,0)
  silkscreen extent -0.86,-0.86 0.87,0.86
USB3.0-A-Receptacle [mm]
  round 3.5 hole 2.4: 0(-3.07,-2) 0(10.07,-2)
  round 1.2 hole 0.6: 1(0,0) 2(2.5,0) 3(4.5,0) 4(7,0) 5(7.5,1.5) 6(5.5,1.5) 7(3.5,1.5) 8(1.5,1.5) 9(-0.5,1.5)
  silkscreen extent -3.14,-14.04 10.07,2.85
WFBGA-169-14x18x0.8mm [mm]
  round 0.3 smd: A4(1.5,3.5) A6(2.5,3.5) A9(4,3.5) A11(5,3.5) AA1(0,-6.5) AA3(1,-6.5) AA4(1.5,-6.5) AA5(2,-6.5) AA6(2.5,-6.5) AA7(3,-6.5) AA8(3.5,-6.5) AA9(4,-6.5) AA10(4.5,-6.5) AA11(5,-6.5) AA12(5.5,-6.5) AA13(6,-6.5) AA14(6.5,-6.5) AE1(0,-8.5) AE14(6.5,-8.5) AG2(0.5,-9.5) AG13(6,-9.5) AH4(1.5,-10) AH6(2.5,-10) AH9(4,-10) AH11(5,-10) B2(0.5,3) B13(6,3) D1(0,2) D14(6.5,2) H3(1,0) H4(1.5,0) H5(2,0) H7(3,0) H8(3.5,0) H9(4,0) H10(4.5,0) H11(5,0) H12(5.5,0) H13(6,0) H14(6.5,0) J1(0,-0.5) J2(0.5,-0.5) J3(1,-0.5) J4(1.5,-0.5) J5(2,-0.5) J6(2.5,-0.5) J7(3,-0.5) J8(3.5,-0.5) J9(4,-0.5) J10(4.5,-0.5) J11(5,-0.5) J12(5.5,-0.5) J13(6,-0.5) J14(6.5,-0.5) K2(0.5,-1) K4(1.5,-1) K5(2,-1) K6(2.5,-1) K7(3,-1) K8(3.5,-1) K9(4,-1) K10(4.5,-1) K11(5,-1) K12(5.5,-1) K13(6,-1) K14(6.5,-1) L1(0,-1.5) L2(0.5,-1.5) L4(1.5,-1.5) L12(5.5,-1.5) L13(6,-1.5) L14(6.5,-1.5) M1(0,-2) M2(0.5,-2) M3(1,-2) M5(2,-2) M6(2.5,-2) M7(3,-2) M8(3.5,-2) M9(4,-2) M10(4.5,-2) M12(5.5,-2) M13(6,-2) M14(6.5,-2) N1(0,-2.5) N2(0.5,-2.5) N3(1,-2.5) N5(2,-2.5) N10(4.5,-2.5) N12(5.5,-2.5) N13(6,-2.5) N14(6.5,-2.5) P1(0,-3) P2(0.5,-3) P3(1,-3) P5(2,-3) P10(4.5,-3) P12(5.5,-3) P13(6,-3) P14(6.5,-3) R1(0,-3.5) R2(0.5,-3.5) R3(1,-3.5) R5(2,-3.5) R10(4.5,-3.5) R12(5.5,-3.5) R13(6,-3.5) R14(6.5,-3.5) T1(0,-4) T2(0.5,-4) T3(1,-4) T5(2,-4) T10(4.5,-4) T12(5.5,-4) T13(6,-4) T14(6.5,-4) U1(0,-4.5) U2(0.5,-4.5) U3(1,-4.5) U5(2,-4.5) U8(3.5,-4.5) U9(4,-4.5) U10(4.5,-4.5) U12(5.5,-4.5) U13(6,-4.5) U14(6.5,-4.5) V1(0,-5) V2(0.5,-5) V3(1,-5) V12(5.5,-5) V13(6,-5) V14(6.5,-5) W1(0,-5.5) W2(0.5,-5.5) W3(1,-5.5) W4(1.5,-5.5) W5(2,-5.5) W6(2.5,-5.5) W7(3,-5.5) W8(3.5,-5.5) W9(4,-5.5) W10(4.5,-5.5) W11(5,-5.5) W12(5.5,-5.5) W13(6,-5.5) W14(6.5,-5.5) Y1(0,-6) Y2(0.5,-6) Y3(1,-6) Y4(1.5,-6) Y5(2,-6) Y6(2.5,-6) Y7(3,-6) Y8(3.5,-6) Y9(4,-6) Y10(4.5,-6) Y11(5,-6) Y12(5.5,-6) Y13(6,-6) Y14(6.5,-6)
  round 0.27 smd: ""(-2,-9) ""(-2,-8.5) ""(-2,-8) ""(-2,-7.5) ""(-2,-7) ""(-2,-6.5) ""(-2,-6) ""(-2,-0.5) ""(-2,0) ""(-2,0.5) ""(-2,1) ""(-2,1.5) ""(-2,2) ""(-2,2.5) ""(-1.5,-6) ""(-1.5,-9) ""(-1.5,-8.5) ""(-1.5,-8) ""(-1.5,-7.5) ""(-1.5,-7) ""(-1.5,-6.5) ""(-1.5,-0.5) ""(-1.5,0) ""(-1.5,0.5) ""(-1.5,1) ""(-1.5,1.5) ""(-1.5,2) ""(-1.5,2.5) ""(-1,-9) ""(-1,2.5) ""(7.5,-9) ""(7.5,2.5) ""(8,-9) ""(8,-8.5) ""(8,-8) ""(8,-7.5) ""(8,-7) ""(8,-6.5) ""(8,-6) ""(8,-0.5) ""(8,0) ""(8,0.5) ""(8,1) ""(8,1.5) ""(8,2) ""(8,2.5) ""(8.5,-9) ""(8.5,-8.5) ""(8.5,-8) ""(8.5,-7.5) ""(8.5,-7) ""(8.5,-6.5) ""(8.5,-6) ""(8.5,-0.5) ""(8.5,0) ""(8.5,0.5) ""(8.5,1) ""(8.5,1.5) ""(8.5,2) ""(8.5,2.5)
  silkscreen extent -3.76,-12.25 10.25,5.75

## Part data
C1 C2 C7 C13 C14: library part cap, "Capacitor"
C3 C4 C5 C6 C8 C9 C10 C11 C12 C15 C16 C17 C18 C19 C20 C21 C22 C23 C24 C25 C26 C27 C28 C29 C30 C31 C32 C33 C34 C35 C36 C37 C38 C39 C40 C41 C42 C43 C44 C45 C46 C47 C48 C49 C50 C51 C52 C53 C54 C55 C56 C57 C58 C59 C60 C62 C63 C64 C65 C66 C68 C69 C70 C71 C72 C73 C74 C75: library part CAP, "Capacitor"
C61 C67: library part CAPACITOR, "Capacitor"
D1: "Typical RED GaAs LED"
D2 D4: library part "0805 蓝灯", "发光二极管"
D3: library part "0805 翠绿", "发光二极管"
D5: library part "0805 黄灯", "发光二极管"
F1 F2: library part FUSE1, "Fuse"
FMI1: library part PT8351
J1: library part CON2, "Connector"
J3 J4 J6: "Connector"
J5: library part USB-AF3.0-90卷
L1 L3 L7: library part INDUCTOR
L5 L6: library part Inductor, "Inductor"
P3 P4: "Header, 2-Pin"
P5: "Header, 5-Pin"
P6: "Header, 11-Pin, Dual row"
R1 R2 R3 R4 R5 R6 R7 R8 R9 R10 R11 R12 R13 R14 R15 R16 R17 R18 R19 R23 R24 R27 R28 R29 R30 R31 R32 R33 R34 R35 R36 R37 R38 R39 R40 R43 R44 R45 R46 R47 R48 R49 R50 R52 R53 R54 R55 R56 R57 R58 R59 R60 R61 R62 R63 R64 R65 R66 R67 R68 R69 R70 R71 R72 R73 R81 R82 R83 R84 R88 R89 R90: library part Res
R20 R21 R22 R25 R26 R85 R86 R87: library part Res2, "Resistor"
R41 R42 R51 R76 R80: library part R-8P4R, "贴片网络排阻"
R74 R75 R77 R78 R79: library part R
S1 S2: "Switch"
S3: "SPDT Subminiature Toggle Switch, Right Angle Mounting, Vertical Actuation"
tp1 tp2: "测试点"
U4: "32bit RISC-V MCU with USB 3.0 SS/HS & quad UART & AES & ETH & DVP"
U5: library part RTL8211FS(I), "千兆以太网物理层芯片"
U8: library part Pro89C.tmp_25F512_2
X1: library part 晶体
X2: library part XTAL-2P, "2脚无源脚晶振"

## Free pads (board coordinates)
  round 137.8 hole 118.11: 0(144.36,143.12) 0(144.36,3793.89) 0(3792.65,3793.89) 0(3792.65,143.12)
  round 32 hole 20: ""(104.69,1361.92) ""(104.69,1408.95) ""(104.69,1455.97) ""(104.69,1502.99) ""(104.69,1550.01) ""(154.01,1361.92) ""(154.01,1408.95) ""(154.01,1455.97) ""(154.01,1502.99) ""(154.01,1550.01) ""(203.33,1361.92) ""(203.33,1408.95) ""(203.33,1455.97) ""(203.33,1502.99) ""(203.33,1550.01) ""(252.64,1361.92) ""(252.64,1408.95) ""(252.64,1455.97) ""(252.64,1502.99) ""(252.64,1550.01)
  rect 220x260 smd far side: ""(186.59,1454.12)
  oct 180x180 hole 140: ""(3119.01,3813.24)

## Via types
v1: diameter 17.72, hole 7.87, Top Layer to Bottom Layer, 556 vias
v2: diameter 24, hole 12, Top Layer to Bottom Layer, 366 vias
v3: diameter 28, hole 16, Top Layer to Bottom Layer, 63 vias
v4: diameter 17.72, hole 7.87, Top Layer to Bottom Layer, tented both sides, 8 vias
v5: diameter 24, hole 12, Top Layer to Bottom Layer, tented both sides, 5 vias
v6: diameter 26, hole 14, Top Layer to Bottom Layer, 2 vias
v7: diameter 19.68, hole 10, Top Layer to Bottom Layer, 1 vias
v8: diameter 20, hole 10, Top Layer to Bottom Layer, 1 vias
v9: diameter 28, hole 16, Top Layer to Bottom Layer, tented both sides, 1 vias
v10: diameter 32, hole 18, Top Layer to Bottom Layer, 1 vias
v11: diameter 17.72, hole 12, Top Layer to Bottom Layer, 1 vias

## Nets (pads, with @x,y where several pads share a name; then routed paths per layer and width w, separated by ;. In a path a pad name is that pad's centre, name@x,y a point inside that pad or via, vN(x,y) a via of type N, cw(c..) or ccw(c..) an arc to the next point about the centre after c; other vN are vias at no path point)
1V2: C14.2 C36.2 C38.2 C49.2 C50.2 R90.2 U4.6 U4.9 U4.63 | length 1926.6
  Top Layer w6: 1991.15,1500.63 1991.15,1560.14 U4.6@1991.35,1560.34 1991.35,1510.76 ; U4.9@2038.15,1559.9 U4.9@2038.59,1560.34 2038.59,1550.01 ccw(c2079.67,1550.01) v8@2050.63,1520.96 ; 1991.35,1510.76 ccw(c2022.85,1510.76) v5(2000.58,1488.49) 1991.35,1497.71 1991.35,1510.76
  Top Layer w6.07: v3(1793,1686) ccw(c1831.92,1724.92) 1831.92,1669.88 U4.63@1880.41,1669.88
  Top Layer w30: R90.2@1211.8,1079.72 1220.56,1088.48 ccw(c1149.85,1159.19) 1249.85,1159.19 C14.2@1249.85,1181.08 1519.59,1181.08 1546.13,1181.08 ccw(c1546.13,1181.85) v3(1546.9,1181.85)
  Layer 2 w20: v3(1519.59,1181.85) v3(1546.9,1181.85) 1570.22,1181.85 ccw(c1570.22,1271.76) 1633.8,1208.18 1763.71,1338.09 ccw(c1693,1408.8) 1793,1408.8 1793,1480.29 ; 1793,1571.94 1793,1564.52 ; v3(1793,1686) 1793,1564.52 ; v5(2000.58,1488.49) 1990.41,1498.65 ccw(c1919.7,1427.94) 1919.7,1527.94 1840.65,1527.94 ; 1793,1480.29 cw(c1840.65,1480.29) 1840.65,1527.94 ; 1793,1480.29 1793,1527.94 ; 1793,1527.94 1793,1564.52 ; 1793,1527.94 1829.58,1527.94 ; 1793,1564.52 ccw(c1829.58,1564.52) 1829.58,1527.94 ; 1829.58,1527.94 1840.65,1527.94
  Layer 2 w30: v5(2000.58,1488.49) ccw(c2000.58,1518.85) 2022.05,1497.38 v8(2049.13,1524.46)
  Bottom Layer w20: C36.2@1814.62,1691.49 C38.2@1814.62,1755.37
  Bottom Layer w30: C49.2@1999.49,1518.66 1999.49,1491.11 ccw(c2003.2,1491.11) v5(2000.58,1488.49) ; v8(2049.13,1524.46) 2054.09,1529.42 ccw(c2020.25,1563.26) C50.2@2068.11,1563.26
2V5: C7.2 C8.2 R84.1 U2.2 | length 737.7
  Top Layer w30: U2.2@398.07,1455.16 544.41,1455.16 cw(c544.41,1422.82) C8.2@567.28,1445.69 567.28,1387.32 ccw(c622.64,1387.32) C7.2@583.5,1348.18 583.5,1309.09 ccw(c616.29,1309.09) 593.1,1285.9 ccw(c644.76,1337.57) 644.76,1264.5 705.85,1264.5 ccw(c705.85,1364.5) 776.56,1293.79 889.39,1406.62 ccw(c850.99,1445.02) R84.1@905.3,1445.02
3V3: C2.2 C65.2 C67.1 C68.1 C69.1 J4.3 JP1.2 P3.1 P5.5 R2.2 R9.1 R13.1 R17.1 R52.2 R64.2 R65.2 R81.2 R82.2 R83.2 R85.1 R89.2 U7.M6 U7.N5 U7.T10 U7.U9 U8.3 U8.7 U8.8 | length 16449.5
  Top Layer w6: v4(3481.78,3005.34) cw(c3486.82,3002.07) 3486.82,3008.07 3491.86,3008.07 3499.89,3016.11 U7.N5@3501.47,3016.11 3502.58,3017.22 3512.48,3017.22 3520.04,3024.78 3520.04,3034.68 U7.M6@3521.15,3035.79 ; U7.U9@3580.21,2937.37 v5@3580.21,2948.61 ; v5@3580.21,2948.61 cw(c3589,2948.61) v5(3582.78,2954.83)
  Top Layer w30: v3(428.7,366.52) cw(c427.24,367.97) v3@427.24,365.91 ; R89.2@687.96,1079.72 ccw(c646.67,1121.01) 705.06,1121.01 C2.2@705.06,1181.08 ; R85.1@905.3,1307.5 828.43,1230.63 ; v3(2330.32,3210.65) ccw(c2336.04,3216.36) 2336.04,3208.28 R9.1@2403.9,3208.28 ; v3(2365.45,3210.79) 2397.84,3210.79 cw(c2397.84,3202.22) R9.1@2403.9,3208.28 ; R17.1@2403.9,3137.48 R9.1@2403.9,3208.28 ; R81.2@2557.01,885.2 R83.2@2775.75,885.2 v3@2775.75,817.11 ; v3(2956.04,712.11) ccw(c2957.33,713.39) 2957.33,711.58 U8.3@3035.36,711.58 3150.75,711.58 ccw(c3150.75,773.38) 3194.46,729.68 3231.96,767.18 cw(c3235.23,763.92) 3235.23,768.54 ; R64.2@3125.26,1248.07 R65.2@3125.26,1185.93 3072.71,1185.93 ccw(c3072.71,1143.91) 3042.99,1173.62 ccw(c3088.65,1127.97) 3024.08,1127.97 3024.08,1036.5 ccw(c3114.78,1036.5) 3050.65,972.37 ccw(c3090.21,1011.93) 3090.21,955.98 3279.7,955.98 ; U8.7@3305.36,761.58 3249.54,761.58 cw(c3249.54,779.32) 3236.99,766.77 3235.23,768.54 ; R52.2@3447.84,897.08 3447.84,917.53 ; JP1.2@3612.66,509.23 ccw(c3695.27,509.23) 3636.86,450.82 3645.59,442.08 ccw(c3678.06,474.56) 3678.06,428.64 3730.51,428.64 ccw(c3730.51,515.9) 3792.2,454.19 3793.02,455 ccw(c3722.31,525.71) 3822.31,525.71 3822.31,875.62 ccw(c3722.31,875.62) 3793.02,946.33 J4.3@3713.66,1025.68 3713.66,1008.86 cw(c3652.76,1008.86) 3695.83,965.79 cw(c3672.13,989.49) 3672.13,955.98 3472.25,955.98 ; v3@427.24,365.92 ccw(c425.11,368.05) 428.13,368.05 v3(428.13,396.51) cw(c420.76,396.51) 425.98,391.32 R2.2@400.58,365.91 v3@427.24,365.91 ; C2.2@705.06,1181.08 cw(c725.32,1181.08) 725.32,1201.34 v3(751.84,1201.34) 757.72,1201.34 ccw(c757.72,1301.34) 828.43,1230.63 ; C2.2@705.06,1181.08 ccw(c736.34,1212.36) 736.34,1168.12 v3(751.84,1168.12) ccw(c751.84,1202.09) 775.87,1178.07 808.16,1210.36 ; C2.2@705.06,1181.08 737.45,1181.08 ccw(c737.45,1281.08) 751.84,1182.12 ccw(c737.45,1281.08) 808.16,1210.36 ; 808.16,1210.36 828.43,1230.63 ; 3235.23,768.54 cw(c3251.27,784.58) 3228.58,784.58 cw(c3256.05,784.58) 3236.63,804 3238.48,805.85 cw(c3252.31,792.01) 3252.31,811.58 U8.8@3305.36,811.58 3305.36,862.12 cw(c3352.04,862.12) C65.2@3319.03,895.12 3319.03,916.64 ; 3279.7,955.98 cw(c3279.7,916.64) 3319.03,916.64 ; 3279.7,955.98 3346.53,955.98 ; 3319.03,916.64 3319.03,925.21 cw(c3352.13,925.21) 3328.73,948.61 cw(c3346.53,930.81) 3346.53,955.98 ; 3346.53,955.98 3409.39,955.98 ; 3409.39,955.98 cw(c3409.39,917.53) 3447.84,917.53 ; 3409.39,955.98 3472.25,955.98 ; 3447.84,917.53 3447.84,931.57 ; 3447.84,931.57 cw(c3472.25,931.57) 3472.25,955.98 ; 3447.84,931.57 3447.84,933.16 cw(c3469.54,933.16) 3454.2,948.5 cw(c3472.25,930.45) 3472.25,955.98
  Layer 2 w30: v3@738.25,1168.52 534.82,965.09 ccw(c605.53,894.38) 505.53,894.38 505.53,880.38 ; v3(2330.32,3210.65) 2330.47,3210.79 v3(2365.45,3210.79) 2496.32,3210.79 ccw(c2496.32,3310.79) 2567.03,3240.08 2739.49,3412.54 cw(c2810.2,3341.82) 2810.2,3441.82 3540.1,3441.82 cw(c3540.1,3341.82) 3610.81,3412.54 3648.75,3374.6 cw(c3578.04,3303.89) 3678.04,3303.89 3678.04,3062.14 cw(c3578.04,3062.14) 3648.75,2991.43 3632.91,2975.6 cw(c3582.78,3025.73) v5(3582.78,2954.83) ; 2878.79,790.77 ccw(c2815.19,727.17) 2815.19,817.11 ; v3(2956.04,712.11) 2920.83,747.33 cw(c2923.23,749.73) 2919.83,749.73 ; JP1.2@3612.66,509.23 3612.66,162.58 cw(c3548.79,162.58) 3593.95,117.41 3588.94,112.4 cw(c3518.23,183.11) 3518.23,83.11 P5.5@2985.09,83.11 2985.09,108.35 ccw(c2949.52,108.35) 2974.67,133.5 2968.33,139.84 ccw(c2897.62,69.13) 2897.62,169.13 2465.66,169.13 ccw(c2465.66,69.13) 2394.95,139.84 2340.91,85.8 cw(c2270.2,156.51) 2270.2,56.51 635.13,56.51 cw(c635.13,156.51) 564.41,85.8 456.15,194.06 cw(c523.81,261.72) 428.13,261.72 428.13,324.53 ; 428.13,324.53 cw(c528.13,324.53) 457.42,395.24 ; 428.13,324.53 v3@428.13,367.89 ; v3@428.13,367.89 ccw(c430.07,367.89) v3(428.7,366.52) 457.42,395.24 ; v3@428.13,367.89 v3(428.13,396.51) 476.24,444.63 ccw(c405.53,515.34) 505.53,515.34 ; 457.42,395.24 476.24,414.06 ccw(c405.53,484.77) 505.53,484.77 505.53,515.34 ; 505.53,515.34 505.53,880.38 ; 505.53,880.38 cw(c605.53,880.38) 534.82,951.09 v3(751.84,1168.12) 751.84,1182.12 ; v3@738.3,1168.57 ccw(c705.44,1201.34) v3(751.84,1201.34) ; v3@738.3,1168.57 ccw(c705.44,1201.34) v3(751.84,1201.34) ; v3@738.3,1168.57 751.84,1182.12 ; 751.84,1182.12 v3(751.84,1201.34) ; 2776,833.06 2776.68,833.06 cw(c2776.68,778.6) 2815.19,817.11 ; 2776,833.06 2776,817.23 v3(2775.88,817.11) 2815.19,817.11 ; 2776,833.06 v3(2776,848.9) 2779.24,848.9 cw(c2779.24,748.9) 2849.95,819.61 2919.83,749.73 ; 2919.83,749.73 2940.42,729.13 ccw(c2983.39,772.1) v3@2958.19,716.81 ; v3@2958.19,716.81 ccw(c2971.4,730.02) 2971.4,711.34 v3(2983.39,711.34) cw(c2983.39,772.1) v3@2958.19,716.81
  Bottom Layer w15: C67.1@3486.52,3021.86 3486.52,3064.43 cw(c3512.04,3064.43) 3494,3082.48 cw(c3505.7,3070.78) 3505.7,3087.32 3514.38,3087.32 cw(c3514.38,3061.32) 3532.77,3079.71 3538.02,3074.45 cw(c3526.21,3062.63) 3542.92,3062.63 3542.92,3059.96 ccw(c3566.55,3059.96) 3549.84,3043.25 3571.45,3021.64 ccw(c3611.87,3062.07) C69.1@3611.87,3004.9
  Bottom Layer w30: v3(751.84,1168.12) v3(751.84,1201.34) 751.84,1297.11 cw(c851.84,1297.11) 781.13,1367.82 814.68,1401.37 ccw(c743.97,1472.08) 843.97,1472.08 P3.1@843.97,1597.92 821.06,1597.92 cw(c821.06,1679.02) 763.71,1621.67 cw(c792.35,1650.31) 751.84,1650.31 751.84,1702.51 ccw(c651.84,1702.51) 722.55,1773.22 526.23,1969.55 cw(c596.94,2040.26) 496.94,2040.26 496.94,2224.13 cw(c596.94,2224.13) 526.23,2294.84 704.05,2472.66 cw(c774.76,2401.95) 774.76,2501.95 793.96,2501.95 ccw(c793.96,2601.95) 864.67,2531.24 920.51,2587.08 ccw(c849.8,2657.79) 949.8,2657.79 R13.1@949.8,2674.67 1016.51,2674.67 cw(c1016.51,2574.67) 1087.22,2645.38 1106.42,2626.18 ccw(c1171.66,2691.42) 1171.66,2599.16 1427.09,2599.16 ccw(c1427.09,2699.16) 1497.8,2628.45 1530.92,2661.56 ccw(c1460.21,2732.27) 1560.21,2732.27 1560.21,3006.08 cw(c1660.21,3006.08) 1589.5,3076.79 1838.81,3326.1 cw(c1909.52,3255.39) 1909.52,3355.39 2277.01,3355.39 cw(c2277.01,3270.61) 2336.96,3330.56 cw(c2268.17,3261.77) 2365.45,3261.77 ; v5(3582.78,2954.83) 3613.39,2954.83 ccw(c3613.39,2961.21) C68.1@3617.9,2956.7 cw(c3632.46,2971.26) 3611.87,2971.26 C69.1@3611.87,3004.9 ; 2365.45,3261.77 cw(c2326.82,3261.77) 2354.13,3234.46 v3(2330.32,3210.65) 2365.3,3210.65 v3(2365.45,3210.79) 2365.45,3261.77
3X1-IN: C48.2 U4.68 X1.1 | length 353.8
  Top Layer w6.07: C48.2@1698.26,1317 ccw(c1678.14,1337.12) 1706.6,1337.12 X1.1@1706.6,1402.13 1754.91,1450.44 ccw(c1731.17,1474.18) 1764.74,1474.18 cw(c1812.51,1474.18) 1778.73,1507.95 1848.84,1578.06 cw(c1880.41,1546.48) U4.68@1880.41,1591.14
3X1-OUT: C47.1 U4.67 X1.3 | length 363.1
  Top Layer w6.07: C47.1@1558.97,1474.18 cw(c1603.64,1429.51) 1603.64,1492.68 X1.3@1631.8,1492.68 1668.59,1529.48 cw(c1722.97,1475.1) 1722.97,1552 1753.22,1552 ccw(c1753.22,1652) 1823.93,1581.29 1828.94,1586.3 cw(c1878.64,1536.59) 1878.64,1606.89 U4.67@1880.41,1606.89
5V: C3.2 C5.2 C6.2 C11.2 F1.2 J4.1 R12.1 U1.1 U1.4 U2.3 U3(NC).1 U3(NC).4 | length 9657.1
  Top Layer w30: F1.2@190.92,1235.6 219.03,1207.5 cw(c148.32,1136.78) C3.2@248.32,1136.78 ; v3(313.43,209.71) 368,155.15 368.27,155.15 ; v3@338.44,184.98 368.27,155.15 ; U2.3@398.07,1541.16 465.13,1541.16 cw(c465.13,1475.33) 492.72,1535.1 ; U1.4@407.67,852.63 407.67,833.28 cw(c373.53,833.28) 397.67,809.13 394.81,806.27 cw(c368.36,832.71) 368.36,795.32 366.07,795.32 ccw(c366.07,762.44) 342.83,785.69 ; 934.8,852.58 cw(c862.54,852.58) 913.63,801.48 cw(c901.43,813.69) 901.43,796.43 891.05,796.43 ccw(c891.05,765.5) 869.19,787.38 864.76,782.94 ccw(c876.26,771.44) 860,771.44 860,742.39 786.07,742.39 cw(c786.07,785.48) C11.2@755.6,755.01 665.33,664.74 cw(c594.62,735.45) 594.62,635.45 400.69,635.45 cw(c400.69,704.73) 351.7,655.74 cw(c397.17,701.21) 332.87,701.21 U1.1@332.87,742.39 ; v3(3050.32,472.54) 3050.32,492.23 ccw(c3036.78,492.23) v3(3046.36,501.81) 3046.36,308.56 cw(c2946.36,308.56) 3017.07,237.84 2995.64,216.41 cw(c2924.93,287.13) 2924.93,187.13 2536.81,187.13 ccw(c2536.81,87.13) 2466.1,157.84 2429.37,121.11 cw(c2358.66,191.82) 2358.66,91.82 473.02,91.82 cw(c473.02,191.82) 402.31,121.11 368.27,155.15 ; C3.2@248.32,1131.85 ccw(c248.32,1181.23) 283.24,1146.31 v3(288.72,1151.79) v3(288.72,1112.36) 249.61,1112.36 ccw(c249.61,1110.54) 248.32,1111.83 C3.2@248.32,1131.85 ; C3.2@248.32,1131.85 C3.2@248.32,1136.78 ; C3.2@248.32,1136.78 ccw(c269.67,1115.43) 239.47,1115.43 239.47,876.44 ccw(c291.62,876.44) 254.69,839.62 ; 254.69,839.62 ccw(c291.62,876.44) 254.75,839.56 ; 254.69,839.62 cw(c206.75,791.56) 254.75,839.56 ; 254.75,839.56 284.44,809.87 ccw(c342.83,868.25) 308.9,792.98 ; 308.9,792.98 ccw(c342.83,868.25) 342.83,785.69 ; 308.9,792.98 314.05,787.83 cw(c268.6,742.39) U1.1@332.87,742.39 ; U1.1@332.87,742.39 332.87,761.65 cw(c366.87,761.65) 342.83,785.69 ; 492.72,1535.1 ccw(c526.08,1568.46) 508.86,1524.54 ; 492.72,1535.1 cw(c465.13,1475.33) 508.86,1524.54 ; 508.86,1524.54 ccw(c526.08,1568.46) 518.61,1521.88 ccw(c526.08,1568.46) 526.08,1521.29 C6.2@567.28,1521.29 567.28,1574.17 cw(c622.64,1574.17) C5.2@583.5,1613.32 C5.2@578.46,1613.32 ; C5.2@578.46,1613.32 cw(c578.46,1669.8) v3(538.53,1629.86) cw(c536.96,1628.29) 539.17,1628.29 v3(539.17,1599.22) cw(c573.21,1565.19) 573.21,1613.32 C5.2@578.46,1613.32
  Layer 2 w30: v3(337.7,184.24) 259.35,262.6 cw(c330.06,333.31) 230.06,333.31 230.06,1012.28 cw(c330.06,1012.28) 259.35,1082.99 v3(288.72,1112.36) ; v3(538.53,1629.86) 538.53,1443.02 cw(c438.53,1443.02) 509.24,1372.31 316.6,1179.68 ; v3(3046.36,501.81) v3@3050.32,505.78 ; J4.1@3513.66,1025.68 3490.67,1002.69 ccw(c3561.38,931.98) 3461.38,931.98 3461.38,679.35 cw(c3361.38,679.35) 3432.09,608.64 3388.18,564.73 cw(c3317.47,635.44) 3317.47,535.44 3137.14,535.44 ; v3(288.72,1112.36) cw(c383.92,1112.36) 316.57,1179.64 ; v3(288.72,1112.36) v3(288.72,1151.79) 316.57,1179.64 ; v3@3050.32,505.78 3050.7,506.15 cw(c3121.41,435.44) 3083.12,527.82 cw(c3121.41,435.44) 3121.41,535.44 3137.14,535.44 ; v3@3050.32,505.78 v3(3050.32,472.54) 3096.31,518.53 cw(c3137.14,477.69) 3137.14,535.44
  Bottom Layer w30: 307.01,1869.07 307.01,1872.81 ; 307.01,1897.5 307.01,1872.81 ; R12.1@855.52,2663.68 R12.1@855.52,2674.67 802.59,2621.75 cw(c731.88,2692.46) 731.88,2592.46 443.06,2592.46 ccw(c443.06,2533.01) 401.03,2575.05 336.3,2510.31 ccw(c407.01,2439.6) 307.01,2439.6 307.01,1872.81 ; 307.01,1872.81 ccw(c407.01,1872.81) 336.3,1802.1 487.33,1651.07 ; 487.33,1651.07 ccw(c538.53,1702.26) v3(538.53,1629.86) 538.53,1600.79 ccw(c540.74,1600.79) v3(539.17,1599.22) 487.33,1651.07
AVDD10: C41.2 C42.2 C43.2 R54.2 U5.4 U5.9 U5.47 | length 2134.4
  Top Layer w6: v1@1877.48,2381.42 U5.9@1919.13,2381.42 ; v7(1877.48,2460.36) 1877.68,2460.16 U5.4@1919.13,2460.16
  Top Layer w8: v3@1886.66,2591.64 1893.18,2598.15 cw(c1913.61,2577.72) 1913.61,2606.61 1932.42,2606.61 cw(c1932.42,2571.53) 1957.23,2596.34 cw(c1935.17,2574.28) 1966.37,2574.28 U5.47@1966.37,2538.9
  Top Layer w30: v3(2516.69,2522.02) v3@2516.92,2521.79 ; R54.2@2688.84,2484.02 2632.97,2484.02 ; v3@2516.92,2521.79 v3(2550.78,2521.79) 2553.78,2521.79 2562.26,2513.31 ccw(c2632.97,2584.02) 2632.97,2484.02 ; v3@2516.92,2521.79 2525.4,2513.31 ccw(c2596.11,2584.02) 2596.11,2484.02 2632.97,2484.02
  Layer 2 w20: 1822.64,2535.71 cw(c1861.34,2535.71) 1833.97,2563.07 1871.26,2600.36 ; 1822.64,2535.71 v3(1807.95,2535.71) cw(c1848.38,2535.71) 1819.79,2564.3 v3(1855.85,2600.36) 1871.26,2600.36 ; 1822.64,2535.71 1837.33,2535.71 cw(c1837.33,2532.29) v3(1839.74,2534.71) cw(c1884.95,2534.71) 1852.98,2566.68 v3(1886.66,2600.36) 1871.26,2600.36
  Layer 2 w30: v3(1886.66,2600.36) 2429.66,2600.36 ; v3@2537.69,2522.02 ccw(c2459.35,2522.02) 2516.53,2575.57 ; 2429.66,2600.36 cw(c2429.66,2504.14) 2497.69,2572.18 cw(c2451.83,2526.32) 2516.69,2526.32 v3(2516.69,2522.02) 2516.92,2521.79 v3(2550.78,2521.79) ccw(c2503.65,2521.79) 2536.98,2555.11 2516.53,2575.57 ; 2429.66,2600.36 2459.35,2600.36 cw(c2459.35,2522.02) 2516.53,2575.57
  Bottom Layer w20: v3(1855.85,2600.36) v3(1886.66,2600.36) ; v1@1877.48,2381.68 cw(c1877.48,2448.09) 1830.52,2401.13 C42.2@1830.37,2401.28 C43.2@1830.37,2467.37 ; v7(1877.48,2460.36) 1847.3,2460.36 cw(c1847.3,2484.29) C43.2@1830.37,2467.37 ; C43.2@1830.37,2467.37 1830.37,2512.09 ; 1830.37,2512.09 ccw(c1827.49,2512.09) 1829.53,2514.13 v3(1807.95,2535.71) ccw(c1810.36,2538.12) 1810.36,2534.71 v3(1839.74,2534.71) ccw(c1862.36,2512.09) 1830.37,2512.09
  Bottom Layer w30: v3(1886.66,2600.36) cw(c1886.66,2586.51) 1896.45,2596.3 C41.2@1910.29,2582.46
  other v1: 1877.48,2380.68
AVDD33: C15.2 C16.2 R9.2 R10.1 U5.1 U5.12 | length 2190.9
  Top Layer w6: v6(1882.06,2522.15) ccw(c1917.67,2557.76) 1917.67,2507.41 U5.1@1919.13,2507.41
  Top Layer w8: v2(1830.46,2307.55) ccw(c1830.46,2345.89) 1857.57,2318.78 1863.2,2324.41 cw(c1886.79,2300.81) 1886.79,2334.18 U5.12@1919.13,2334.18
  Top Layer w20: 2422.47,3275.57 2367.83,3275.57 ; 2456.64,3267.71 ccw(c2437.66,3248.7) 2437.66,3275.57 2367.83,3275.57 ; 2456.66,3267.7 cw(c2437.66,3248.7) 2464.53,3248.7 R9.2@2464.53,3208.28 R10.1@2533.95,3208.28 ; 2367.83,3275.57 cw(c2367.83,3374.24) v3(2298.06,3304.47) 2306.29,3296.23 cw(c2285.63,3275.57) v3(2314.86,3275.57) 2367.83,3275.57
  Bottom Layer w20: v2(1830.46,2307.55) 1830.37,2307.64 C16.2@1830.37,2335.2 1877.6,2335.2 ccw(c1877.6,2373.89) 1904.96,2346.53 ccw(c1872.53,2378.96) 1918.4,2378.96 1918.4,2496.2 ccw(c1890.72,2496.2) C15.2@1910.29,2515.77 1897.48,2515.77 cw(c1897.48,2537.57) v6(1882.06,2522.15) 1882.06,2530.38 ccw(c1847.34,2530.38) 1871.89,2554.93 1866.79,2560.03 ccw(c1850.57,2543.81) 1850.57,2566.75 cw(c1850.57,2618.23) 1814.17,2581.83 1805.37,2590.62 cw(c1838.2,2623.45) 1791.78,2623.45 1791.78,2799.72 cw(c1891.78,2799.72) 1821.07,2870.43 2196.91,3246.28 ; 2257.51,3287.29 2298.19,3287.29 cw(c2298.19,3275.37) 2306.59,3283.83 cw(c2327.29,3304.47) v3(2298.06,3304.47) 2296.52,3304.47 ccw(c2296.52,3204.47) 2238.71,3286.06 ; v3@2306.62,3283.8 v3(2314.86,3275.57) ; v3@2316.86,3275.57 v3(2314.86,3275.57) ; 2196.91,3246.28 cw(c2267.62,3175.57) 2267.62,3275.57 ; 2196.91,3246.28 2225.81,3275.18 cw(c2296.52,3204.47) 2238.71,3286.06 ; 2238.71,3286.06 ccw(c2264.06,3311.41) 2264.06,3275.57 2267.62,3275.57 ; 2267.62,3275.57 v3(2314.86,3275.57)
CK125M: R62.1 U5.44 | length 438.4
  Top Layer w6: R62.1@1833.08,2915.44 1850.71,2897.82 cw(c1779.99,2827.1) 1879.99,2827.1 1879.99,2781.41 ccw(c1979.99,2781.41) 1909.28,2710.7 1984.32,2635.66 cw(c1913.61,2564.95) 2013.61,2564.95 U5.44@2013.61,2538.9
CLK_1: R34.1 R41.8 R78.2 U4.31 | length 2702.9
  Top Layer w6: U4.31@2196.78,1795.86 2254.11,1795.86 ccw(c2254.11,1895.86) 2288.95,1802.13 ccw(c2254.11,1895.86) 2324.82,1825.15 2327.71,1828.03 cw(c2375.59,1780.15) 2375.59,1847.87 2426.43,1847.87 2426.43,1888.16 cw(c2526.43,1888.16) 2526.43,1988.16 2785.32,1988.16 ccw(c2785.32,2088.16) 2885.32,2088.16 2885.32,2118.59 2885.32,2121.59 ccw(c2879.02,2121.59) 2879.02,2127.89 2872.55,2127.89 cw(c2872.55,2134.19) 2866.25,2134.19 2866.25,2135.59 cw(c2872.55,2135.59) 2872.55,2141.89 2903.88,2141.89 ccw(c2903.88,2148.19) 2910.18,2148.19 2910.18,2149.59 ccw(c2903.88,2149.59) 2903.88,2155.89 2872.55,2155.89 cw(c2872.55,2162.19) 2866.25,2162.19 2866.25,2163.59 cw(c2872.55,2163.59) 2872.55,2169.89 2903.88,2169.89 ccw(c2903.88,2176.19) 2910.18,2176.19 2910.18,2177.59 ccw(c2903.88,2177.59) 2903.88,2183.89 2872.55,2183.89 cw(c2872.55,2190.19) 2866.25,2190.19 2866.25,2191.59 cw(c2872.55,2191.59) 2872.55,2197.89 2903.88,2197.89 ccw(c2903.88,2204.19) 2910.18,2204.19 2910.18,2205.59 ccw(c2903.88,2205.59) 2903.88,2211.89 2872.55,2211.89 cw(c2872.55,2218.19) 2866.25,2218.19 2866.25,2219.59 cw(c2872.55,2219.59) 2872.55,2225.89 2903.88,2225.89 ccw(c2903.88,2232.19) 2910.18,2232.19 2910.18,2233.59 ccw(c2903.88,2233.59) 2903.88,2239.89 2872.55,2239.89 cw(c2872.55,2246.19) 2866.25,2246.19 2866.25,2247.59 cw(c2872.55,2247.59) 2872.55,2253.89 2903.88,2253.89 ccw(c2903.88,2260.19) 2910.18,2260.19 2910.18,2261.59 ccw(c2903.88,2261.59) 2903.88,2267.89 2872.55,2267.89 cw(c2872.55,2274.19) 2866.25,2274.19 2866.25,2275.59 cw(c2872.55,2275.59) 2872.55,2281.89 2903.88,2281.89 ccw(c2903.88,2288.19) 2910.18,2288.19 2910.18,2289.59 ccw(c2903.88,2289.59) 2903.88,2295.89 2872.55,2295.89 cw(c2872.55,2302.19) 2866.25,2302.19 2866.25,2303.59 cw(c2872.55,2303.59) 2872.55,2309.89 2903.88,2309.89 ccw(c2903.88,2316.19) 2910.18,2316.19 2910.18,2317.59 ccw(c2903.88,2317.59) 2903.88,2323.89 2872.55,2323.89 cw(c2872.55,2330.19) 2866.25,2330.19 2866.25,2331.59 cw(c2872.55,2331.59) 2872.55,2337.89 2903.88,2337.89 ccw(c2903.88,2344.19) 2910.18,2344.19 2910.18,2345.59 ccw(c2903.88,2345.59) 2903.88,2351.89 2872.55,2351.89 cw(c2872.55,2358.19) 2866.25,2358.19 2866.25,2359.59 cw(c2872.55,2359.59) 2872.55,2365.89 2903.88,2365.89 ccw(c2903.88,2372.19) 2910.18,2372.19 2910.18,2373.59 ccw(c2903.88,2373.59) 2903.88,2379.89 2872.55,2379.89 cw(c2872.55,2386.19) 2866.25,2386.19 2866.25,2387.59 cw(c2872.55,2387.59) 2872.55,2393.89 2903.88,2393.89 ccw(c2903.88,2400.19) 2910.18,2400.19 2910.18,2401.59 ccw(c2903.88,2401.59) 2903.88,2407.89 2872.55,2407.89 cw(c2872.55,2414.19) 2866.25,2414.19 2866.25,2415.59 cw(c2872.55,2415.59) 2872.55,2421.89 2903.88,2421.89 ccw(c2903.88,2428.19) 2910.18,2428.19 2910.18,2429.59 ccw(c2903.88,2429.59) 2903.88,2435.89 2872.55,2435.89 cw(c2872.55,2442.19) 2866.25,2442.19 2866.25,2443.59 cw(c2872.55,2443.59) 2872.55,2449.89 2903.88,2449.89 ccw(c2903.88,2456.19) 2910.18,2456.19 2910.18,2457.59 ccw(c2903.88,2457.59) 2903.88,2463.89 2872.55,2463.89 cw(c2872.55,2470.19) 2866.25,2470.19 2866.25,2471.59 cw(c2872.55,2471.59) 2872.55,2477.89 2903.88,2477.89 ccw(c2903.88,2484.19) 2910.18,2484.19 2910.18,2485.59 ccw(c2903.88,2485.59) 2903.88,2491.89 2872.55,2491.89 cw(c2872.55,2498.19) 2866.25,2498.19 2866.25,2499.59 cw(c2872.55,2499.59) 2872.55,2505.89 2903.88,2505.89 ccw(c2903.88,2512.19) 2910.18,2512.19 2910.18,2513.59 ccw(c2903.88,2513.59) 2903.88,2519.89 2872.55,2519.89 cw(c2872.55,2526.19) 2866.25,2526.19 2866.25,2527.59 cw(c2872.55,2527.59) 2872.55,2533.89 2903.88,2533.89 ccw(c2903.88,2540.19) 2910.18,2540.19 2910.18,2541.59 ccw(c2903.88,2541.59) 2903.88,2547.89 2872.55,2547.89 cw(c2872.55,2554.19) 2866.25,2554.19 2866.25,2555.59 cw(c2872.55,2555.59) 2872.55,2561.89 2903.88,2561.89 ccw(c2903.88,2568.19) 2910.18,2568.19 2910.18,2569.59 ccw(c2903.88,2569.59) 2903.88,2575.89 2872.55,2575.89 cw(c2872.55,2582.19) 2866.25,2582.19 2866.25,2583.59 cw(c2872.55,2583.59) 2872.55,2589.89 2879.02,2589.89 ccw(c2879.02,2596.19) 2885.32,2596.19 2885.32,2618.32 R78.2@2885.32,2673.67
  other v2: 2399.96,1845.76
